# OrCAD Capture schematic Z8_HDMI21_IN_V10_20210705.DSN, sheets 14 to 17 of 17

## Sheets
14 PAGE14-10AX032-(3C&3D): size C
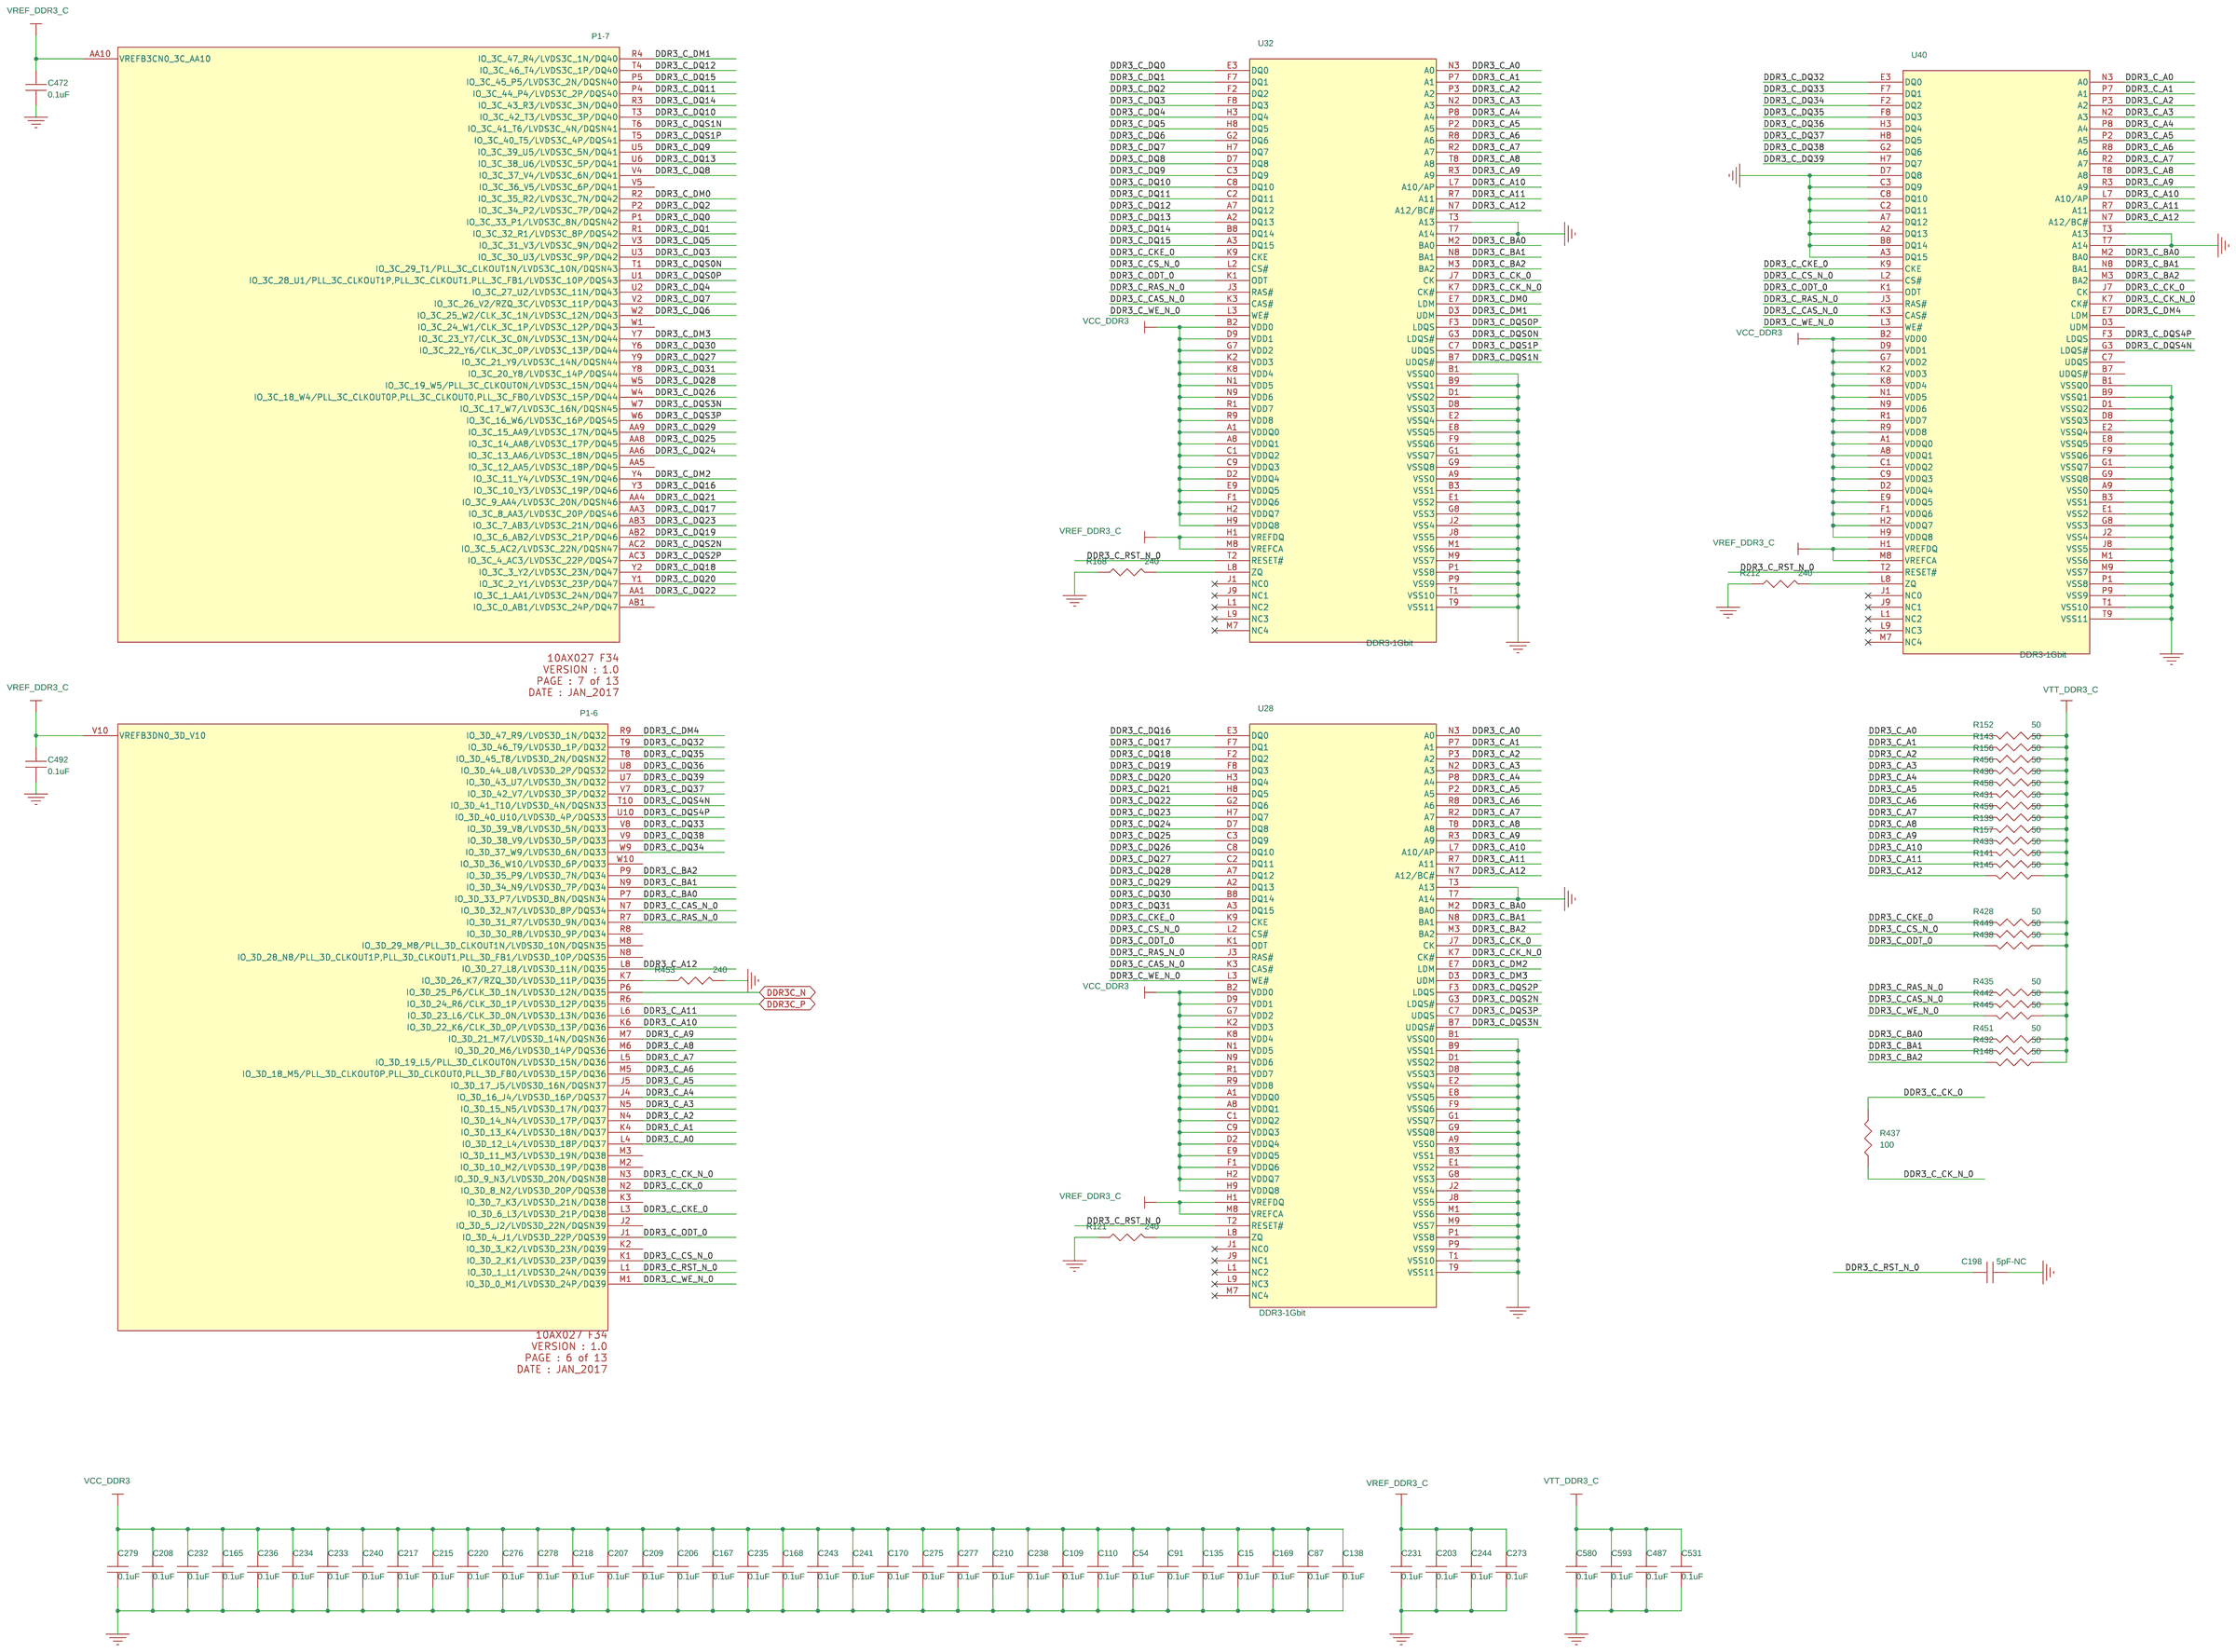
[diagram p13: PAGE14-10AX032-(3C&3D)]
15 PAGE13-10AX032-(3A&3B): size C
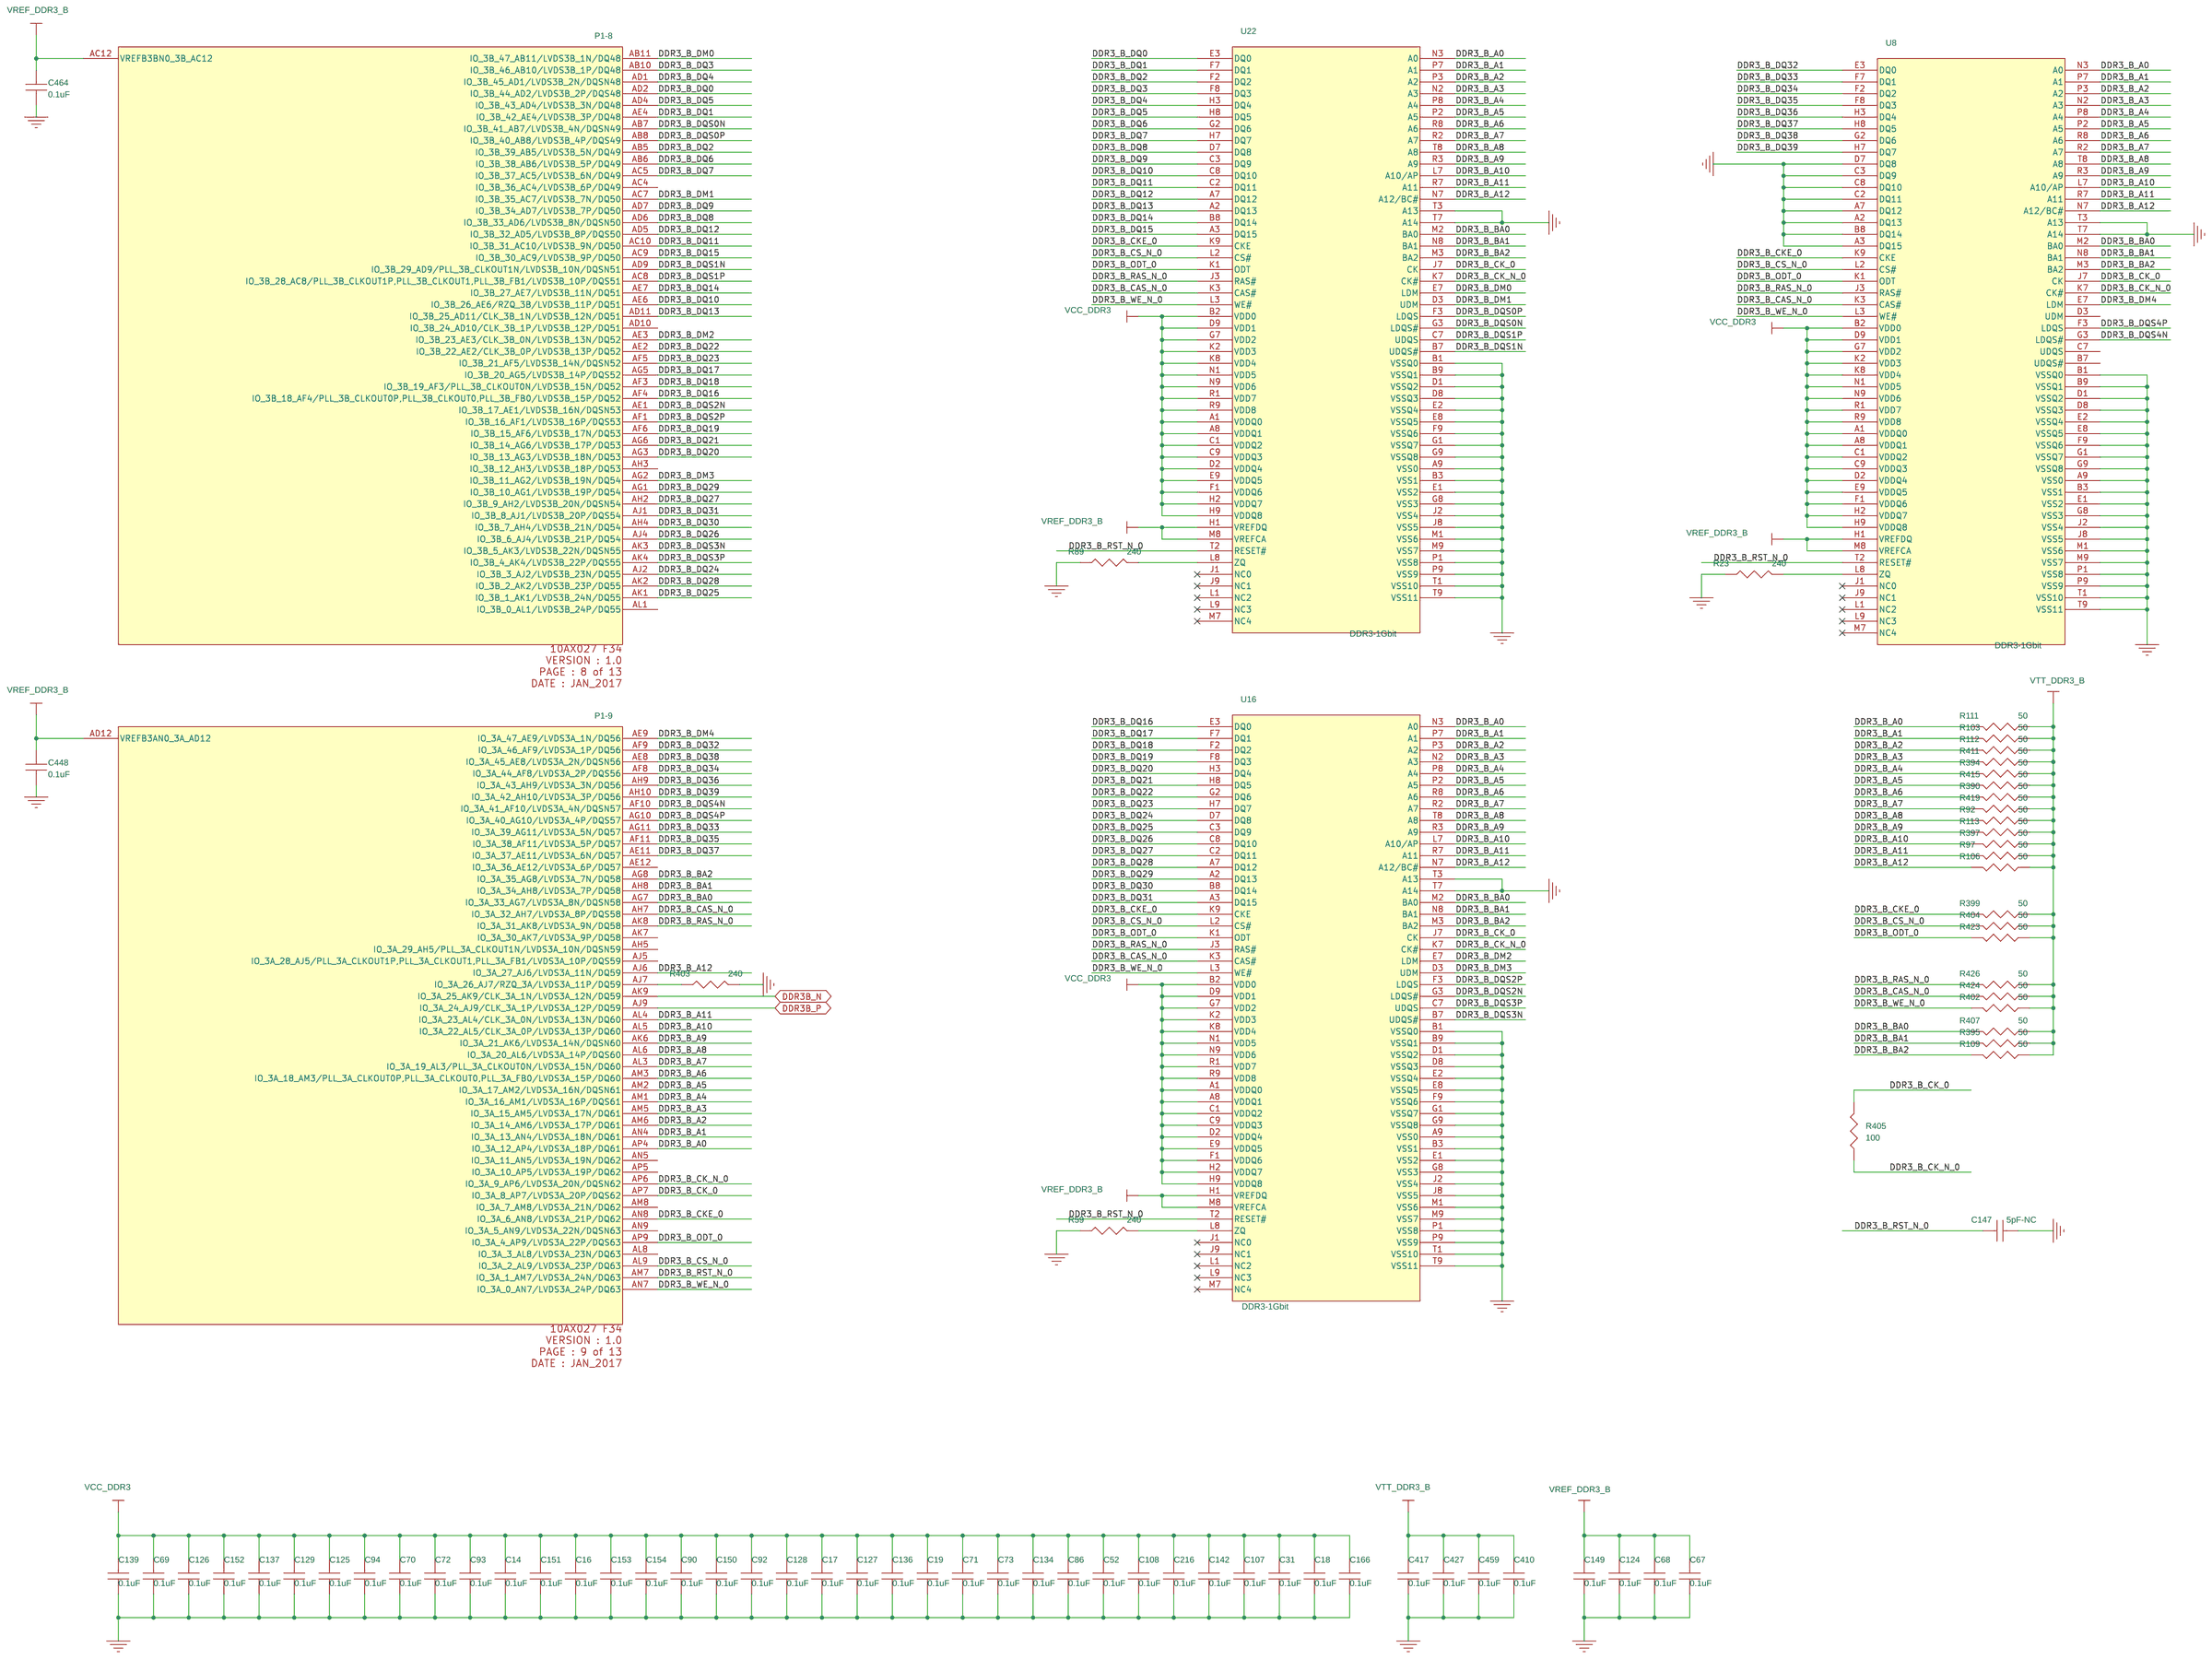
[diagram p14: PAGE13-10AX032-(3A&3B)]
16 PAGE16-10AX032-PWR&GND: size D
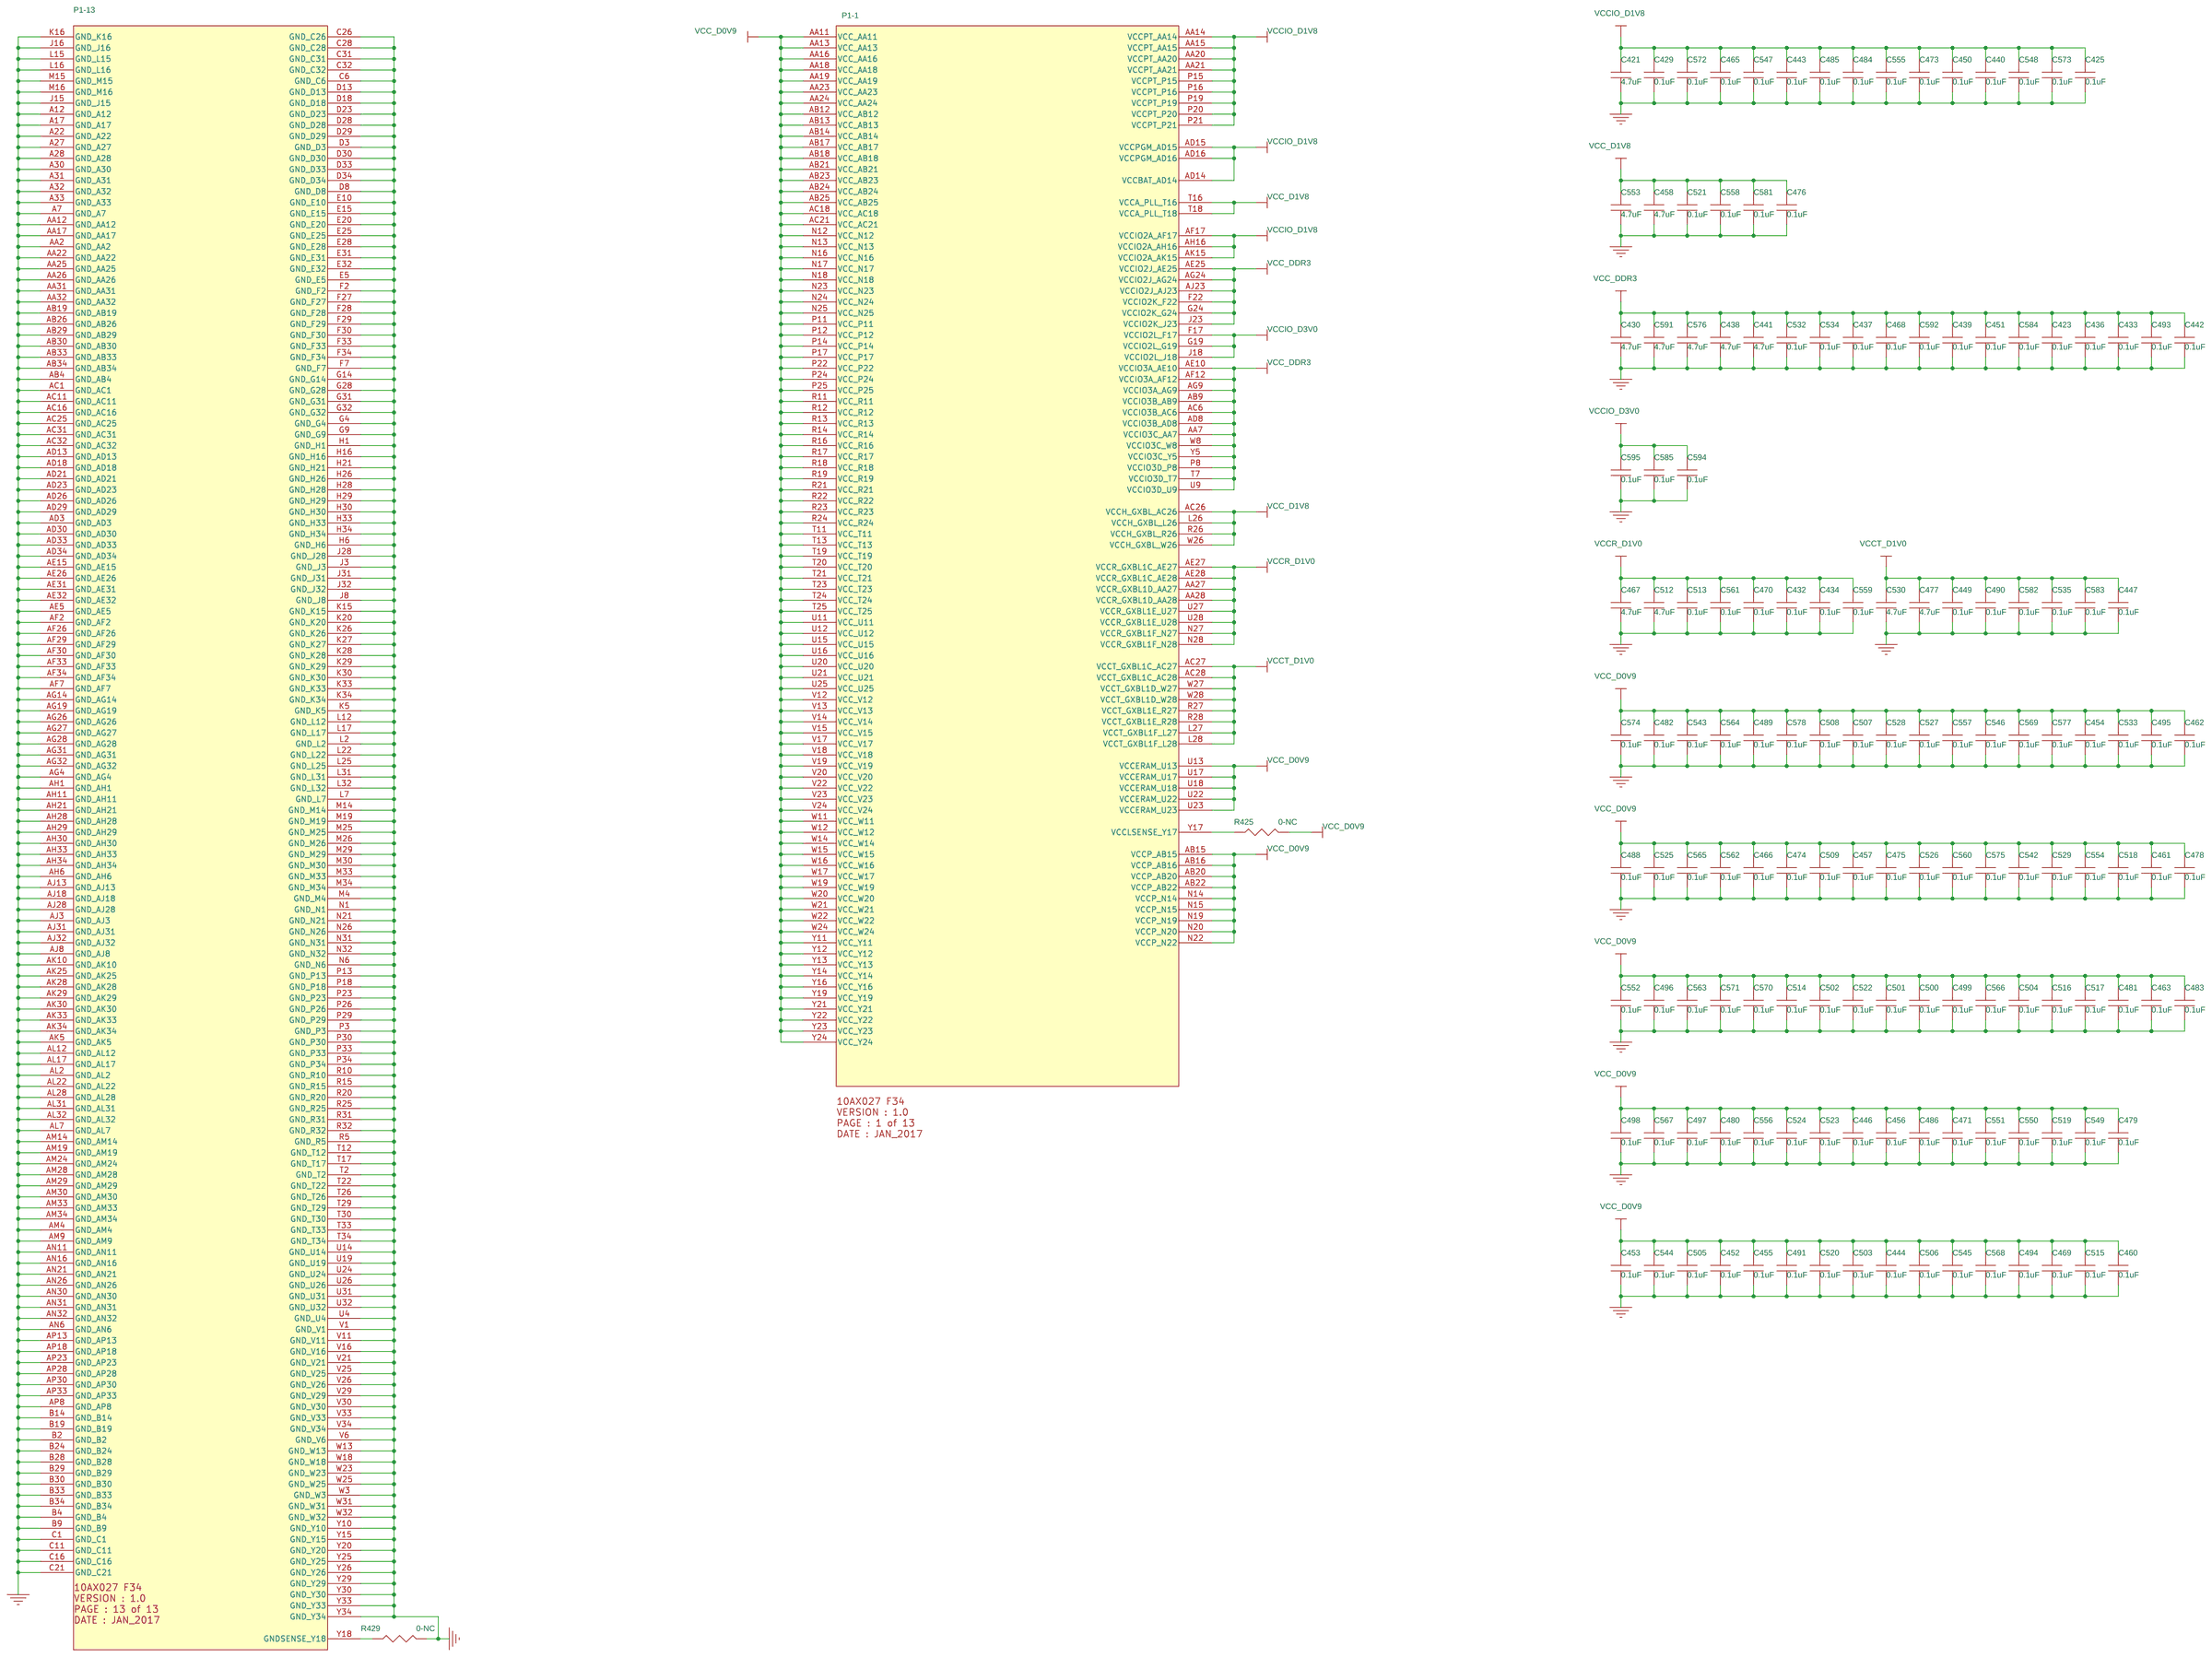
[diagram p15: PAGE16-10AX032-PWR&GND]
17 PAGE03-FPGA PWR: size Custom
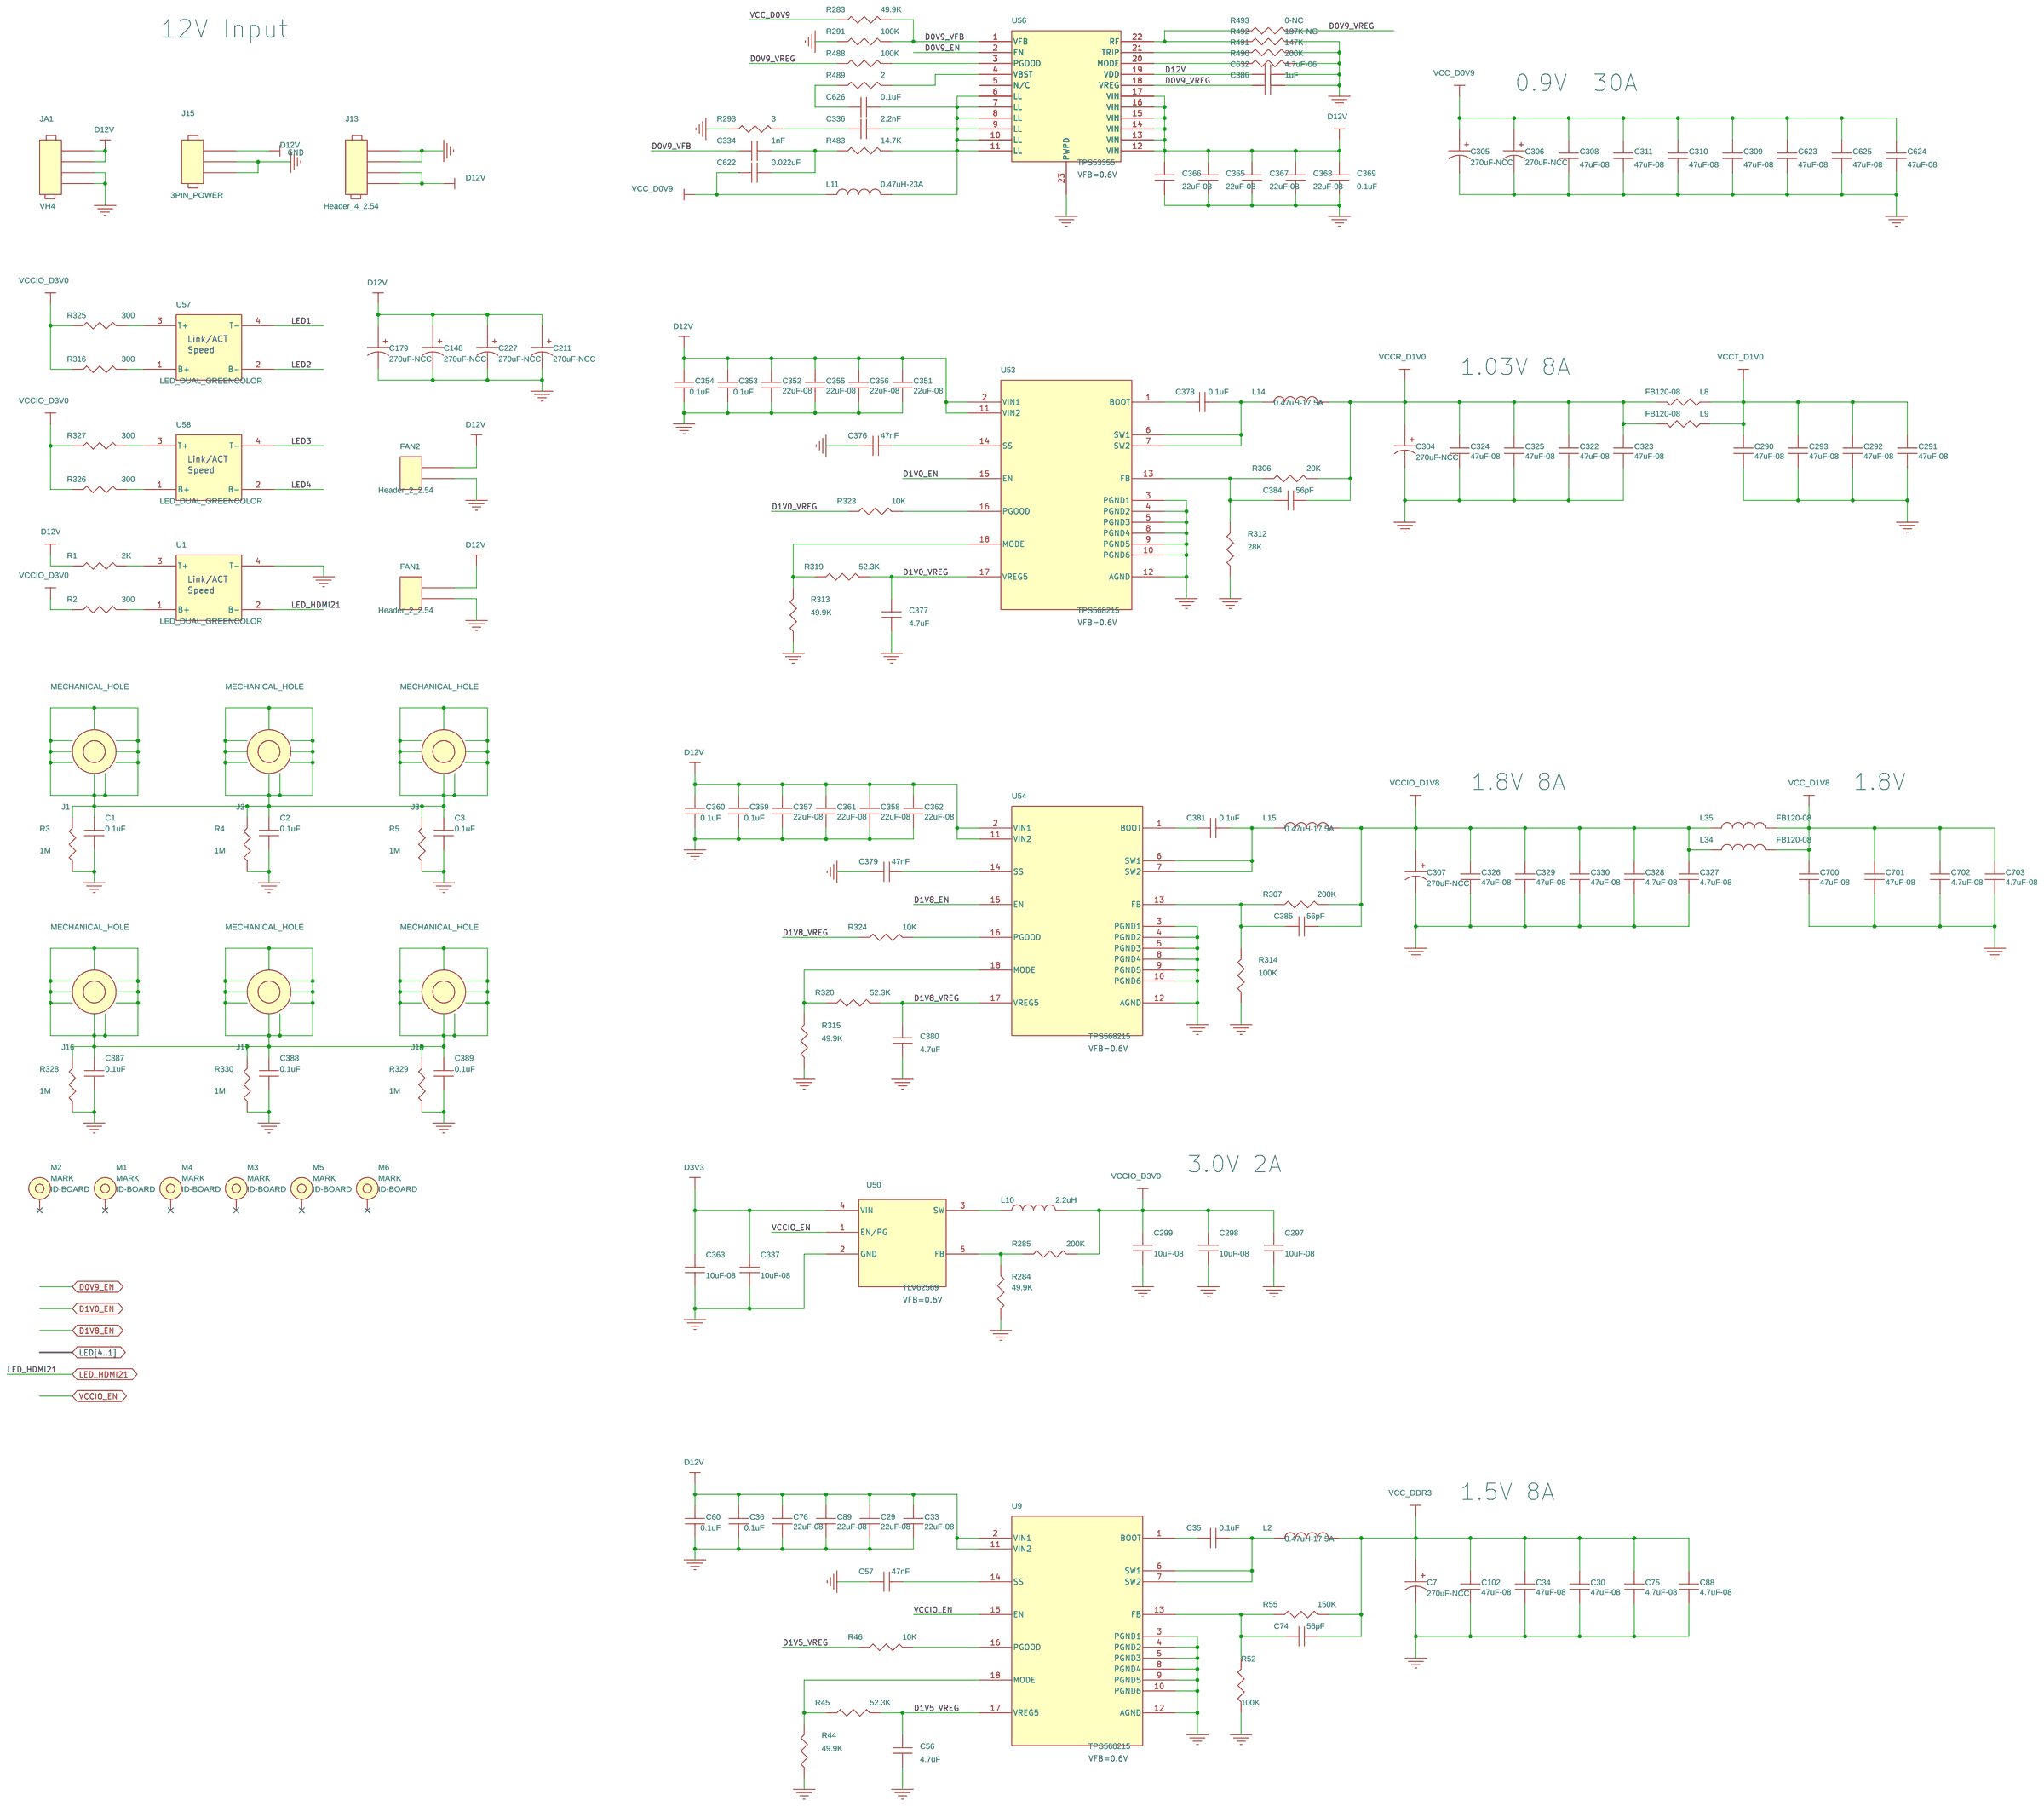
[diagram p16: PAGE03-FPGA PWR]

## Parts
sheet PAGE03-FPGA PWR
C1  0.1uF  [C0402]
C2  0.1uF  [C0402]
C3  0.1uF  [C0402]
C7  270uF-NCC  [cap196_pol_3_5mm]
C29  22uF-08  [C0805]
C30  47uF-08  [C0805]
C33  22uF-08  [C0805]
C34  47uF-08  [C0805]
C35  0.1uF  [C0402]
C36  0.1uF  [C0402]
C56  4.7uF  [C0402]
C57  47nF  [C0402]
C60  0.1uF  [C0402]
C74  56pF  [C0402]
C75  4.7uF-08  [C0603]
C76  22uF-08  [C0805]
C88  4.7uF-08  [C0603]
C89  22uF-08  [C0805]
C102  47uF-08  [C0805]
C148  270uF-NCC  [cap196_pol_3_5mm]
C179  270uF-NCC  [cap196_pol_3_5mm]
C211  270uF-NCC  [cap196_pol_3_5mm]
C227  270uF-NCC  [cap196_pol_3_5mm]
C290  47uF-08  [C0805]
C291  47uF-08  [C0805]
C292  47uF-08  [C0805]
C293  47uF-08  [C0805]
C297  10uF-08  [C0805]
C298  10uF-08  [C0805]
C299  10uF-08  [C0805]
C304  270uF-NCC  [cap196_pol_3_5mm]
C305  270uF-NCC  [cap196_pol_3_5mm]
C306  270uF-NCC  [cap196_pol_3_5mm]
C307  270uF-NCC  [cap196_pol_3_5mm]
C308  47uF-08  [C0805]
C309  47uF-08  [C0805]
C310  47uF-08  [C0805]
C311  47uF-08  [C0805]
C322  47uF-08  [C0805]
C323  47uF-08  [C0805]
C324  47uF-08  [C0805]
C325  47uF-08  [C0805]
C326  47uF-08  [C0805]
C327  4.7uF-08  [C0603]
C328  4.7uF-08  [C0603]
C329  47uF-08  [C0805]
C330  47uF-08  [C0805]
C334  1nF  [C0402]
C336  2.2nF  [C0402]
C337  10uF-08  [C0805]
C351  22uF-08  [C0805]
C352  22uF-08  [C0805]
C353  0.1uF  [C0402]
C354  0.1uF  [C0402]
C355  22uF-08  [C0805]
C356  22uF-08  [C0805]
C357  22uF-08  [C0805]
C358  22uF-08  [C0805]
C359  0.1uF  [C0402]
C360  0.1uF  [C0402]
C361  22uF-08  [C0805]
C362  22uF-08  [C0805]
C363  10uF-08  [C0805]
C365  22uF-08  [C0805]
C366  22uF-08  [C0805]
C367  22uF-08  [C0805]
C368  22uF-08  [C0805]
C369  0.1uF  [C0402]
C376  47nF  [C0402]
C377  4.7uF  [C0402]
C378  0.1uF  [C0402]
C379  47nF  [C0402]
C380  4.7uF  [C0402]
C381  0.1uF  [C0402]
C384  56pF  [C0402]
C385  56pF  [C0402]
C386  1uF  [C0402]
C387  0.1uF  [C0402]
C388  0.1uF  [C0402]
C389  0.1uF  [C0402]
C622  0.022uF  [C0402]
C623  47uF-08  [C0805]
C624  47uF-08  [C0805]
C625  47uF-08  [C0805]
C626  0.1uF  [C0402]
C632  4.7uF-06  [C0603]
C700  47uF-08  [C0805]
C701  47uF-08  [C0805]
C702  4.7uF-08  [C0603]
C703  4.7uF-08  [C0603]
FAN1  Header_2_2.54  [conn1x2_2_54]
FAN2  Header_2_2.54  [conn1x2_2_54]
J1  MECHANICAL_HOLE  [TOOL_1H_8D_C_LC_02]
J2  MECHANICAL_HOLE  [TOOL_1H_8D_C_LC_02]
J3  MECHANICAL_HOLE  [TOOL_1H_8D_C_LC_02]
J13  Header_4_2.54  [conn1x4_2_54]
J15  3PIN_POWER  [3PIN_POWER]
J16  MECHANICAL_HOLE  [TOOL_1H_8D_C_LC_02]
J17  MECHANICAL_HOLE  [TOOL_1H_8D_C_LC_02]
J18  MECHANICAL_HOLE  [TOOL_1H_8D_C_LC_02]
JA1  VH4  [DRILL_1x4_3_96]
L2  0.47uH-17.5A  [l_gfb_58x28]
L8  FB120-08  [R0805]
L9  FB120-08  [R0805]
L10  2.2uH  [IND4X4]
L11  0.47uH-23A  [l_gfb_58x28]
L14  0.47uH-17.5A  [l_gfb_58x28]
L15  0.47uH-17.5A  [l_gfb_58x28]
L34  FB120-08  [R0805]
L35  FB120-08  [R0805]
M1  MARK  [ID-BOARD]
M2  MARK  [ID-BOARD]
M3  MARK  [ID-BOARD]
M4  MARK  [ID-BOARD]
M5  MARK  [ID-BOARD]
M6  MARK  [ID-BOARD]
R1  2K  [R0402]
R2  300  [R0402]
R3  1M  [R0402]
R4  1M  [R0402]
R5  1M  [R0402]
R44  49.9K  [R0402]
R45  52.3K  [R0402]
R46  10K  [R0402]
R52  100K  [R0402]
R55  150K  [R0402]
R283  49.9K  [R0402]
R284  49.9K  [R0402]
R285  200K  [R0402]
R291  100K  [R0402]
R293  3  [R0402]
R306  20K  [R0402]
R307  200K  [R0402]
R312  28K  [R0402]
R313  49.9K  [R0402]
R314  100K  [R0402]
R315  49.9K  [R0402]
R316  300  [R0402]
R319  52.3K  [R0402]
R320  52.3K  [R0402]
R323  10K  [R0402]
R324  10K  [R0402]
R325  300  [R0402]
R326  300  [R0402]
R327  300  [R0402]
R328  1M  [R0402]
R329  1M  [R0402]
R330  1M  [R0402]
R483  14.7K  [R0402]
R488  100K  [R0402]
R489  2  [R0402]
R490  200K  [R0402]
R491  147K  [R0402]
R492  187K-NC  [R0402]
R493  0-NC  [R0402]
U1  LED_DUAL_GREENCOLOR  [LED-4p]
U9  TPS568215  [TPS568215]
U50  TLV62569  [sot23-5]
U53  TPS568215  [TPS568215]
U54  TPS568215  [TPS568215]
U56  TPS53355  [DQP_N22]
U57  LED_DUAL_GREENCOLOR  [LED-4p]
U58  LED_DUAL_GREENCOLOR  [LED-4p]
sheet PAGE12-10AX032-(2K&2J)
P1  10AX027 F34  [BGA1152_PAD18]  (sections -1,-10,-11,-12,-13,-2,-3,-4,-5,-6,-7,-8,-9)
sheet PAGE13-10AX032-(3A&3B)
C14  0.1uF  [C0402]
C16  0.1uF  [C0402]
C17  0.1uF  [C0402]
C18  0.1uF  [C0402]
C19  0.1uF  [C0402]
C31  0.1uF  [C0402]
C52  0.1uF  [C0402]
C67  0.1uF  [C0402]
C68  0.1uF  [C0402]
C69  0.1uF  [C0402]
C70  0.1uF  [C0402]
C71  0.1uF  [C0402]
C72  0.1uF  [C0402]
C73  0.1uF  [C0402]
C86  0.1uF  [C0402]
C90  0.1uF  [C0402]
C92  0.1uF  [C0402]
C93  0.1uF  [C0402]
C94  0.1uF  [C0402]
C107  0.1uF  [C0402]
C108  0.1uF  [C0402]
C124  0.1uF  [C0402]
C125  0.1uF  [C0402]
C126  0.1uF  [C0402]
C127  0.1uF  [C0402]
C128  0.1uF  [C0402]
C129  0.1uF  [C0402]
C134  0.1uF  [C0402]
C136  0.1uF  [C0402]
C137  0.1uF  [C0402]
C139  0.1uF  [C0402]
C142  0.1uF  [C0402]
C147  5pF-NC  [C0402]
C149  0.1uF  [C0402]
C150  0.1uF  [C0402]
C151  0.1uF  [C0402]
C152  0.1uF  [C0402]
C153  0.1uF  [C0402]
C154  0.1uF  [C0402]
C166  0.1uF  [C0402]
C216  0.1uF  [C0402]
C410  0.1uF  [C0402]
C417  0.1uF  [C0402]
C427  0.1uF  [C0402]
C448  0.1uF  [C0402-8]
C459  0.1uF  [C0402]
C464  0.1uF  [C0402-8]
R23  240  [R0402]
R59  240  [R0402]
R89  240  [R0402]
R92  50  [R0402]
R97  50  [R0402]
R103  50  [R0402]
R106  50  [R0402]
R109  50  [R0402]
R111  50  [R0402]
R112  50  [R0402]
R113  50  [R0402]
R390  50  [R0402]
R394  50  [R0402]
R395  50  [R0402]
R397  50  [R0402]
R399  50  [R0402]
R402  50  [R0402]
R403  240  [C0402-8]
R404  50  [R0402]
R405  100  [R0402]
R407  50  [R0402]
R411  50  [R0402]
R415  50  [R0402]
R419  50  [R0402]
R423  50  [R0402]
R424  50  [R0402]
R426  50  [R0402]
U8  DDR3-1Gbit  [fbga96-10x14]
U16  DDR3-1Gbit  [fbga96-10x14]
U22  DDR3-1Gbit  [fbga96-10x14]
sheet PAGE14-10AX032-(3C&3D)
C15  0.1uF  [C0402]
C54  0.1uF  [C0402]
C87  0.1uF  [C0402]
C91  0.1uF  [C0402]
C109  0.1uF  [C0402]
C110  0.1uF  [C0402]
C135  0.1uF  [C0402]
C138  0.1uF  [C0402]
C165  0.1uF  [C0402]
C167  0.1uF  [C0402]
C168  0.1uF  [C0402]
C169  0.1uF  [C0402]
C170  0.1uF  [C0402]
C198  5pF-NC  [C0402]
C203  0.1uF  [C0402]
C206  0.1uF  [C0402]
C207  0.1uF  [C0402]
C208  0.1uF  [C0402]
C209  0.1uF  [C0402]
C210  0.1uF  [C0402]
C215  0.1uF  [C0402]
C217  0.1uF  [C0402]
C218  0.1uF  [C0402]
C220  0.1uF  [C0402]
C231  0.1uF  [C0402]
C232  0.1uF  [C0402]
C233  0.1uF  [C0402]
C234  0.1uF  [C0402]
C235  0.1uF  [C0402]
C236  0.1uF  [C0402]
C238  0.1uF  [C0402]
C240  0.1uF  [C0402]
C241  0.1uF  [C0402]
C243  0.1uF  [C0402]
C244  0.1uF  [C0402]
C273  0.1uF  [C0402]
C275  0.1uF  [C0402]
C276  0.1uF  [C0402]
C277  0.1uF  [C0402]
C278  0.1uF  [C0402]
C279  0.1uF  [C0402]
C472  0.1uF  [C0402-8]
C487  0.1uF  [C0402]
C492  0.1uF  [C0402-8]
C531  0.1uF  [C0402]
C580  0.1uF  [C0402]
C593  0.1uF  [C0402]
R121  240  [R0402]
R139  50  [R0402]
R141  50  [R0402]
R143  50  [R0402]
R145  50  [R0402]
R148  50  [R0402]
R152  50  [R0402]
R156  50  [R0402]
R157  50  [R0402]
R168  240  [R0402]
R212  240  [R0402]
R428  50  [R0402]
R430  50  [R0402]
R431  50  [R0402]
R432  50  [R0402]
R433  50  [R0402]
R435  50  [R0402]
R437  100  [R0402]
R438  50  [R0402]
R442  50  [R0402]
R445  50  [R0402]
R449  50  [R0402]
R451  50  [R0402]
R453  240  [C0402-8]
R456  50  [R0402]
R458  50  [R0402]
R459  50  [R0402]
U28  DDR3-1Gbit  [fbga96-10x14]
U32  DDR3-1Gbit  [fbga96-10x14]
U40  DDR3-1Gbit  [fbga96-10x14]
sheet PAGE16-10AX032-PWR&GND
C421  4.7uF  [C0402-8]
C423  0.1uF  [C0402-8]
C425  0.1uF  [C0402-8]
C429  0.1uF  [C0402-8]
C430  4.7uF  [C0402-8]
C432  0.1uF  [C0402-8]
C433  0.1uF  [C0402-8]
C434  0.1uF  [C0402-8]
C436  0.1uF  [C0402-8]
C437  0.1uF  [C0402-8]
C438  4.7uF  [C0402-8]
C439  0.1uF  [C0402-8]
C440  0.1uF  [C0402-8]
C441  4.7uF  [C0402-8]
C442  0.1uF  [C0402-8]
C443  0.1uF  [C0402-8]
C444  0.1uF  [C0402-8]
C446  0.1uF  [C0402-8]
C447  0.1uF  [C0402-8]
C449  0.1uF  [C0402-8]
C450  0.1uF  [C0402-8]
C451  0.1uF  [C0402-8]
C452  0.1uF  [C0402-8]
C453  0.1uF  [C0402-8]
C454  0.1uF  [C0402-8]
C455  0.1uF  [C0402-8]
C456  0.1uF  [C0402-8]
C457  0.1uF  [C0402-8]
C458  4.7uF  [C0402-8]
C460  0.1uF  [C0402-8]
C461  0.1uF  [C0402-8]
C462  0.1uF  [C0402-8]
C463  0.1uF  [C0402-8]
C465  0.1uF  [C0402-8]
C466  0.1uF  [C0402-8]
C467  4.7uF  [C0402-8]
C468  0.1uF  [C0402-8]
C469  0.1uF  [C0402-8]
C470  0.1uF  [C0402-8]
C471  0.1uF  [C0402-8]
C473  0.1uF  [C0402-8]
C474  0.1uF  [C0402-8]
C475  0.1uF  [C0402-8]
C476  0.1uF  [C0402-8]
C477  4.7uF  [C0402-8]
C478  0.1uF  [C0402-8]
C479  0.1uF  [C0402-8]
C480  0.1uF  [C0402-8]
C481  0.1uF  [C0402-8]
C482  0.1uF  [C0402-8]
C483  0.1uF  [C0402-8]
C484  0.1uF  [C0402-8]
C485  0.1uF  [C0402-8]
C486  0.1uF  [C0402-8]
C488  0.1uF  [C0402-8]
C489  0.1uF  [C0402-8]
C490  0.1uF  [C0402-8]
C491  0.1uF  [C0402-8]
C493  0.1uF  [C0402-8]
C494  0.1uF  [C0402-8]
C495  0.1uF  [C0402-8]
C496  0.1uF  [C0402-8]
C497  0.1uF  [C0402-8]
C498  0.1uF  [C0402-8]
C499  0.1uF  [C0402-8]
C500  0.1uF  [C0402-8]
C501  0.1uF  [C0402-8]
C502  0.1uF  [C0402-8]
C503  0.1uF  [C0402-8]
C504  0.1uF  [C0402-8]
C505  0.1uF  [C0402-8]
C506  0.1uF  [C0402-8]
C507  0.1uF  [C0402-8]
C508  0.1uF  [C0402-8]
C509  0.1uF  [C0402-8]
C512  4.7uF  [C0402-8]
C513  0.1uF  [C0402-8]
C514  0.1uF  [C0402-8]
C515  0.1uF  [C0402-8]
C516  0.1uF  [C0402-8]
C517  0.1uF  [C0402-8]
C518  0.1uF  [C0402-8]
C519  0.1uF  [C0402-8]
C520  0.1uF  [C0402-8]
C521  0.1uF  [C0402-8]
C522  0.1uF  [C0402-8]
C523  0.1uF  [C0402-8]
C524  0.1uF  [C0402-8]
C525  0.1uF  [C0402-8]
C526  0.1uF  [C0402-8]
C527  0.1uF  [C0402-8]
C528  0.1uF  [C0402-8]
C529  0.1uF  [C0402-8]
C530  4.7uF  [C0402-8]
C532  0.1uF  [C0402-8]
C533  0.1uF  [C0402-8]
C534  0.1uF  [C0402-8]
C535  0.1uF  [C0402-8]
C542  0.1uF  [C0402-8]
C543  0.1uF  [C0402-8]
C544  0.1uF  [C0402-8]
C545  0.1uF  [C0402-8]
C546  0.1uF  [C0402-8]
C547  0.1uF  [C0402-8]
C548  0.1uF  [C0402-8]
C549  0.1uF  [C0402-8]
C550  0.1uF  [C0402-8]
C551  0.1uF  [C0402-8]
C552  0.1uF  [C0402-8]
C553  4.7uF  [C0402-8]
C554  0.1uF  [C0402-8]
C555  0.1uF  [C0402-8]
C556  0.1uF  [C0402-8]
C557  0.1uF  [C0402-8]
C558  0.1uF  [C0402-8]
C559  0.1uF  [C0402-8]
C560  0.1uF  [C0402-8]
C561  0.1uF  [C0402-8]
C562  0.1uF  [C0402-8]
C563  0.1uF  [C0402-8]
C564  0.1uF  [C0402-8]
C565  0.1uF  [C0402-8]
C566  0.1uF  [C0402-8]
C567  0.1uF  [C0402-8]
C568  0.1uF  [C0402-8]
C569  0.1uF  [C0402-8]
C570  0.1uF  [C0402-8]
C571  0.1uF  [C0402-8]
C572  0.1uF  [C0402-8]
C573  0.1uF  [C0402-8]
C574  0.1uF  [C0402-8]
C575  0.1uF  [C0402-8]
C576  4.7uF  [C0402-8]
C577  0.1uF  [C0402-8]
C578  0.1uF  [C0402-8]
C581  0.1uF  [C0402-8]
C582  0.1uF  [C0402-8]
C583  0.1uF  [C0402-8]
C584  0.1uF  [C0402-8]
C585  0.1uF  [C0402-8]
C591  4.7uF  [C0402-8]
C592  0.1uF  [C0402-8]
C594  0.1uF  [C0402-8]
C595  0.1uF  [C0402-8]
R425  0-NC  [C0402-8]
R429  0-NC  [C0402-8]

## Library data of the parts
C1-C3 C387-C389 = CAP_NP: ROOM: DVI; VOLTAGE: 25V
C7 C148 C179 C211 C227 C304-C307 = CAP_POL
C14-C19 C29-C31 C33-C36 C52 C54 C56 C57 C60 C67-C76 C86-C94 C102 C107-C110 C124-C129 C134-C139 C142 C147 C149-C154 C165-C170 C198 C203 C206-C210 C215-C218 C220 C231-C236 C238 C240 C241 C243 C244 C273 C275-C279 C290-C293 C297-C299 C308-C311 C322-C330 C334 C336 C337 C351-C363 C369 C376-C381 C384-C386 C410 C417 C421 C423 C425 C427 C429 C430 C432-C434 C436-C444 C446-C509 C512-C535 C542-C578 C580-C585 C591-C595 C622-C626 C632 C700-C703 = CAP_NP
C365-C368 = CAPACITOR_NON-POL
FAN1 FAN2 = CONN_FLEX_5_0
J1-J3 J16-J18 = MECHANICAL_HOLE_0
J13 JA1 = 4_HEADER
J15 = 4_HEADER_0
L2 L10 L11 L14 L15 L34 L35 = L_0
L8 L9 R1-R5 R23 R44-R46 R52 R55 R59 R89 R92 R97 R103 R106 R109 R111-R113 R121 R139 R141 R143 R145 R148 R152 R156 R157 R168 R212 R283-R285 R291 R293 R306 R307 R312-R316 R319 R320 R323-R330 R390 R394 R395 R397 R399 R402-R405 R407 R411 R415 R419 R423-R426 R428-R433 R435 R437 R438 R442 R445 R449 R451 R453 R456 R458 R459 R483 R488-R493 = R
M1-M6 = MARK: MARK Symble; Created by: CZD; Priority: A; RK PN: MARK01
U1 U57 U58 = LED_DUAL_BICOLOR
U9 U53 U54 = TPS54040_0
U50 = TLV62565_0
U56 = TPS53355
P1 = 10AX027_F34_2
U8 U16 U22 U28 U32 U40 = DDR3-512MB

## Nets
D0V9_EN: U56.2(EN) ; also on sheet 8
D0V9_VFB: C334.1 R283.1 R291.2 U56.1(VFB)
D0V9_VREG: C386.1 R488.1 R493.2 U56.18(VREG)
D1V0_EN: U53.15(EN) ; also on sheet 8
D1V0_VREG: C377.1 R319.2 R323.1 U53.17(VREG5)
D1V5_VREG: C56.1 R45.2 R46.1 U9.17(VREG5)
D1V8_EN: U54.15(EN) ; also on sheet 8
D1V8_VREG: C380.1 R320.2 R324.1 U54.17(VREG5)
D3V3: C337.1 C363.1 U50.4(VIN) ; also on sheet 1 2 3 5 6 7 8 10
D12V: C29.1 C33.1 C36.1 C60.1 C76.1 C89.1 C148.1 C179.1 C211.1 C227.1 C351.1 C352.1 C353.1 C354.1 C355.1 C356.1 C357.1 C358.1 C359.1 C360.1 C361.1 C362.1 C365.1 C366.1 C367.1 C368.1 C369.1 C632.1 FAN1.1 FAN2.1 J13.3 J13.4 J15.1 JA1.1 JA1.2 R1.1 U9.2(VIN1) U9.11(VIN2) U53.2(VIN1) U53.11(VIN2) U54.2(VIN1) U54.11(VIN2) U56.12(VIN) U56.13(VIN) U56.14(VIN) U56.15(VIN) U56.16(VIN) U56.17(VIN) U56.19(VDD) ; also on sheet 10 12
GND: C1.2 C2.2 C3.2 C7.2 C14.2 C15.2 C16.2 C17.2 C18.2 C19.2 C29.2 C30.2 C31.2 C33.2 C34.2 C36.2 C52.2 C54.2 C56.2 C57.2 C60.2 C67.2 C68.2 C69.2 C70.2 C71.2 C72.2 C73.2 C75.2 C76.2 C86.2 C87.2 C88.2 C89.2 C90.2 C91.2 C92.2 C93.2 C94.2 C102.2 C107.2 C108.2 C109.2 C110.2 C124.2 C125.2 C126.2 C127.2 C128.2 C129.2 C134.2 C135.2 C136.2 C137.2 C138.2 C139.2 C142.2 C147.2 C148.2 C149.2 C150.2 C151.2 C152.2 C153.2 C154.2 C165.2 C166.2 C167.2 C168.2 C169.2 C170.2 C179.2 C198.2 C203.2 C206.2 C207.2 C208.2 C209.2 C210.2 C211.2 C215.2 C216.2 C217.2 C218.2 C220.2 C227.2 C231.2 C232.2 C233.2 C234.2 C235.2 C236.2 C238.2 C240.2 C241.2 C243.2 C244.2 C273.2 C275.2 C276.2 C277.2 C278.2 C279.2 C290.2 C291.2 C292.2 C293.2 C297.2 C298.2 C299.2 C304.2 C305.2 C306.2 C307.2 C308.2 C309.2 C310.2 C311.2 C322.2 C323.2 C324.2 C325.2 C326.2 C327.2 C328.2 C329.2 C330.2 C337.2 C351.2 C352.2 C353.2 C354.2 C355.2 C356.2 C357.2 C358.2 C359.2 C360.2 C361.2 C362.2 C363.2 C365.2 C366.2 C367.2 C368.2 C369.2 C376.2 C377.2 C379.2 C380.2 C386.2 C387.2 C388.2 C389.2 C410.2 C417.2 C421.2 C423.2 C425.2 C427.2 C429.2 C430.2 C432.2 C433.2 C434.2 C436.2 C437.2 C438.2 C439.2 C440.2 C441.2 C442.2 C443.2 C444.2 C446.2 C447.2 C448.2 C449.2 C450.2 C451.2 C452.2 C453.2 C454.2 C455.2 C456.2 C457.2 C458.2 C459.2 C460.2 C461.2 C462.2 C463.2 C464.2 C465.2 C466.2 C467.2 C468.2 C469.2 C470.2 C471.2 C472.2 C473.2 C474.2 C475.2 C476.2 C477.2 C478.2 C479.2 C480.2 C481.2 C482.2 C483.2 C484.2 C485.2 C486.2 C487.2 C488.2 C489.2 C490.2 C491.2 C492.2 C493.2 C494.2 C495.2 C496.2 C497.2 C498.2 C499.2 C500.2 C501.2 C502.2 C503.2 C504.2 C505.2 C506.2 C507.2 C508.2 C509.2 C512.2 C513.2 C514.2 C515.2 C516.2 C517.2 C518.2 C519.2 C520.2 C521.2 C522.2 C523.2 C524.2 C525.2 C526.2 C527.2 C528.2 C529.2 C530.2 C531.2 C532.2 C533.2 C534.2 C535.2 C542.2 C543.2 C544.2 C545.2 C546.2 C547.2 C548.2 C549.2 C550.2 C551.2 C552.2 C553.2 C554.2 C555.2 C556.2 C557.2 C558.2 C559.2 C560.2 C561.2 C562.2 C563.2 C564.2 C565.2 C566.2 C567.2 C568.2 C569.2 C570.2 C571.2 C572.2 C573.2 C574.2 C575.2 C576.2 C577.2 C578.2 C580.2 C581.2 C582.2 C583.2 C584.2 C585.2 C591.2 C592.2 C593.2 C594.2 C595.2 C623.2 C624.2 C625.2 C632.2 C700.2 C701.2 C702.2 C703.2 FAN1.2 FAN2.2 J13.1 J13.2 J15.2 J15.3 JA1.3 JA1.4 P1.A7(GND) P1.A12(GND) P1.A17(GND) P1.A22(GND) P1.A27(GND) P1.A28(GND) P1.A30(GND) P1.A31(GND) P1.A32(GND) P1.A33(GND) P1.AA2(GND) P1.AA12(GND) P1.AA17(GND) P1.AA22(GND) P1.AA25(GND) P1.AA26(GND) P1.AA31(GND) P1.AA32(GND) P1.AB4(GND) P1.AB19(GND) P1.AB26(GND) P1.AB29(GND) P1.AB30(GND) P1.AB33(GND) P1.AB34(GND) P1.AC1(GND) P1.AC11(GND) P1.AC16(GND) P1.AC25(GND) P1.AC31(GND) P1.AC32(GND) P1.AD3(GND) P1.AD13(GND) P1.AD18(GND) P1.AD21(GND) P1.AD23(GND) P1.AD26(GND) P1.AD29(GND) P1.AD30(GND) P1.AD33(GND) P1.AD34(GND) P1.AE5(GND) P1.AE15(GND) P1.AE26(GND) P1.AE31(GND) P1.AE32(GND) P1.AF2(GND) P1.AF7(GND) P1.AF26(GND) P1.AF29(GND) P1.AF30(GND) P1.AF33(GND) P1.AF34(GND) P1.AG4(GND) P1.AG14(GND) P1.AG19(GND) P1.AG26(GND) P1.AG27(GND) P1.AG28(GND) P1.AG31(GND) P1.AG32(GND) P1.AH1(GND) P1.AH6(GND) P1.AH11(GND) P1.AH21(GND) P1.AH28(GND) P1.AH29(GND) P1.AH30(GND) P1.AH33(GND) P1.AH34(GND) P1.AJ3(GND) P1.AJ8(GND) P1.AJ13(GND) P1.AJ18(GND) P1.AJ28(GND) P1.AJ31(GND) P1.AJ32(GND) P1.AK5(GND) P1.AK10(GND) P1.AK25(GND) P1.AK28(GND) P1.AK29(GND) P1.AK30(GND) P1.AK33(GND) P1.AK34(GND) P1.AL2(GND) P1.AL7(GND) P1.AL12(GND) P1.AL17(GND) P1.AL22(GND) P1.AL28(GND) P1.AL31(GND) P1.AL32(GND) P1.AM4(GND) P1.AM9(GND) P1.AM14(GND) P1.AM19(GND) P1.AM24(GND) P1.AM28(GND) P1.AM29(GND) P1.AM30(GND) P1.AM33(GND) P1.AM34(GND) P1.AN6(GND) P1.AN11(GND) P1.AN16(GND) P1.AN21(GND) P1.AN26(GND) P1.AN30(GND) P1.AN31(GND) P1.AN32(GND) P1.AP8(GND) P1.AP13(GND) P1.AP18(GND) P1.AP23(GND) P1.AP28(GND) P1.AP30(GND) P1.AP33(GND) P1.B2(GND) P1.B4(GND) P1.B9(GND) P1.B14(GND) P1.B19(GND) P1.B24(GND) P1.B28(GND) P1.B29(GND) P1.B30(GND) P1.B33(GND) P1.B34(GND) P1.C1(GND) P1.C6(GND) P1.C11(GND) P1.C16(GND) P1.C21(GND) P1.C26(GND) P1.C28(GND) P1.C31(GND) P1.C32(GND) P1.D3(GND) P1.D8(GND) P1.D13(GND) P1.D18(GND) P1.D23(GND) P1.D28(GND) P1.D29(GND) P1.D30(GND) P1.D33(GND) P1.D34(GND) P1.E5(GND) P1.E10(GND) P1.E15(GND) P1.E20(GND) P1.E25(GND) P1.E28(GND) P1.E31(GND) P1.E32(GND) P1.F2(GND) P1.F7(GND) P1.F27(GND) P1.F28(GND) P1.F29(GND) P1.F30(GND) P1.F33(GND) P1.F34(GND) P1.G4(GND) P1.G9(GND) P1.G14(GND) P1.G28(GND) P1.G31(GND) P1.G32(GND) P1.H1(GND) P1.H6(GND) P1.H16(GND) P1.H21(GND) P1.H26(GND) P1.H28(GND) P1.H29(GND) P1.H30(GND) P1.H33(GND) P1.H34(GND) P1.J3(GND) P1.J8(GND) P1.J15(GND) P1.J16(GND) P1.J28(GND) P1.J31(GND) P1.J32(GND) P1.K5(GND) P1.K15(GND) P1.K16(GND) P1.K20(GND) P1.K26(GND) P1.K27(GND) P1.K28(GND) P1.K29(GND) P1.K30(GND) P1.K33(GND) P1.K34(GND) P1.L2(GND) P1.L7(GND) P1.L12(GND) P1.L15(GND) P1.L16(GND) P1.L17(GND) P1.L22(GND) P1.L25(GND) P1.L31(GND) P1.L32(GND) P1.M4(GND) P1.M14(GND) P1.M15(GND) P1.M16(GND) P1.M19(GND) P1.M25(GND) P1.M26(GND) P1.M29(GND) P1.M30(GND) P1.M33(GND) P1.M34(GND) P1.N1(GND) P1.N6(GND) P1.N21(GND) P1.N26(GND) P1.N31(GND) P1.N32(GND) P1.P3(GND) P1.P13(GND) P1.P18(GND) P1.P23(GND) P1.P26(GND) P1.P29(GND) P1.P30(GND) P1.P33(GND) P1.P34(GND) P1.R5(GND) P1.R10(GND) P1.R15(GND) P1.R20(GND) P1.R25(GND) P1.R31(GND) P1.R32(GND) P1.T2(GND) P1.T12(GND) P1.T17(GND) P1.T22(GND) P1.T26(GND) P1.T29(GND) P1.T30(GND) P1.T33(GND) P1.T34(GND) P1.U4(GND) P1.U14(GND) P1.U19(GND) P1.U24(GND) P1.U26(GND) P1.U31(GND) P1.U32(GND) P1.V1(GND) P1.V6(GND) P1.V11(GND) P1.V16(GND) P1.V21(GND) P1.V25(GND) P1.V26(GND) P1.V29(GND) P1.V30(GND) P1.V33(GND) P1.V34(GND) P1.W3(GND) P1.W13(GND) P1.W18(GND) P1.W23(GND) P1.W25(GND) P1.W31(GND) P1.W32(GND) P1.Y10(GND) P1.Y15(GND) P1.Y20(GND) P1.Y25(GND) P1.Y26(GND) P1.Y29(GND) P1.Y30(GND) P1.Y33(GND) P1.Y34(GND) R3.1 R4.1 R5.1 R23.1 R44.1 R52.1 R59.1 R89.1 R121.1 R168.1 R212.1 R284.2 R291.1 R293.1 R312.1 R313.1 R314.1 R315.1 R328.1 R329.1 R330.1 R403.2 R429.1 R453.2 R490.2 R491.2 R492.2 U1.4(T-) U8.A2(DQ13) U8.A3(DQ15) U8.A7(DQ12) U8.A9(VSS0) U8.B1(VSSQ0) U8.B3(VSS1) U8.B8(DQ14) U8.B9(VSSQ1) U8.C2(DQ11) U8.C3(DQ9) U8.C8(DQ10) U8.D1(VSSQ2) U8.D7(DQ8) U8.D8(VSSQ3) U8.E1(VSS2) U8.E2(VSSQ4) U8.E8(VSSQ5) U8.F9(VSSQ6) U8.G1(VSSQ7) U8.G8(VSS3) U8.G9(VSSQ8) U8.J2(VSS4) U8.J8(VSS5) U8.M1(VSS6) U8.M9(VSS7) U8.P1(VSS8) U8.P9(VSS9) U8.T1(VSS10) U8.T3(A13) U8.T7(A14) U8.T9(VSS11) U9.3(PGND1) U9.4(PGND2) U9.5(PGND3) U9.8(PGND4) U9.9(PGND5) U9.10(PGND6) U9.12(AGND) U16.A9(VSS0) U16.B1(VSSQ0) U16.B3(VSS1) U16.B9(VSSQ1) U16.D1(VSSQ2) U16.D8(VSSQ3) U16.E1(VSS2) U16.E2(VSSQ4) U16.E8(VSSQ5) U16.F9(VSSQ6) U16.G1(VSSQ7) U16.G8(VSS3) U16.G9(VSSQ8) U16.J2(VSS4) U16.J8(VSS5) U16.M1(VSS6) U16.M9(VSS7) U16.P1(VSS8) U16.P9(VSS9) U16.T1(VSS10) U16.T3(A13) U16.T7(A14) U16.T9(VSS11) U22.A9(VSS0) U22.B1(VSSQ0) U22.B3(VSS1) U22.B9(VSSQ1) U22.D1(VSSQ2) U22.D8(VSSQ3) U22.E1(VSS2) U22.E2(VSSQ4) U22.E8(VSSQ5) U22.F9(VSSQ6) U22.G1(VSSQ7) U22.G8(VSS3) U22.G9(VSSQ8) U22.J2(VSS4) U22.J8(VSS5) U22.M1(VSS6) U22.M9(VSS7) U22.P1(VSS8) U22.P9(VSS9) U22.T1(VSS10) U22.T3(A13) U22.T7(A14) U22.T9(VSS11) U28.A9(VSS0) U28.B1(VSSQ0) U28.B3(VSS1) U28.B9(VSSQ1) U28.D1(VSSQ2) U28.D8(VSSQ3) U28.E1(VSS2) U28.E2(VSSQ4) U28.E8(VSSQ5) U28.F9(VSSQ6) U28.G1(VSSQ7) U28.G8(VSS3) U28.G9(VSSQ8) U28.J2(VSS4) U28.J8(VSS5) U28.M1(VSS6) U28.M9(VSS7) U28.P1(VSS8) U28.P9(VSS9) U28.T1(VSS10) U28.T3(A13) U28.T7(A14) U28.T9(VSS11) U32.A9(VSS0) U32.B1(VSSQ0) U32.B3(VSS1) U32.B9(VSSQ1) U32.D1(VSSQ2) U32.D8(VSSQ3) U32.E1(VSS2) U32.E2(VSSQ4) U32.E8(VSSQ5) U32.F9(VSSQ6) U32.G1(VSSQ7) U32.G8(VSS3) U32.G9(VSSQ8) U32.J2(VSS4) U32.J8(VSS5) U32.M1(VSS6) U32.M9(VSS7) U32.P1(VSS8) U32.P9(VSS9) U32.T1(VSS10) U32.T3(A13) U32.T7(A14) U32.T9(VSS11) U40.A2(DQ13) U40.A3(DQ15) U40.A7(DQ12) U40.A9(VSS0) U40.B1(VSSQ0) U40.B3(VSS1) U40.B8(DQ14) U40.B9(VSSQ1) U40.C2(DQ11) U40.C3(DQ9) U40.C8(DQ10) U40.D1(VSSQ2) U40.D7(DQ8) U40.D8(VSSQ3) U40.E1(VSS2) U40.E2(VSSQ4) U40.E8(VSSQ5) U40.F9(VSSQ6) U40.G1(VSSQ7) U40.G8(VSS3) U40.G9(VSSQ8) U40.J2(VSS4) U40.J8(VSS5) U40.M1(VSS6) U40.M9(VSS7) U40.P1(VSS8) U40.P9(VSS9) U40.T1(VSS10) U40.T3(A13) U40.T7(A14) U40.T9(VSS11) U50.2(GND) U53.3(PGND1) U53.4(PGND2) U53.5(PGND3) U53.8(PGND4) U53.9(PGND5) U53.10(PGND6) U53.12(AGND) U54.3(PGND1) U54.4(PGND2) U54.5(PGND3) U54.8(PGND4) U54.9(PGND5) U54.10(PGND6) U54.12(AGND) U56.23(PWPD) ; also on sheet 1 2 3 4 5 6 7 8 10 12 13
VCC_D0V9: C305.1 C306.1 C308.1 C309.1 C310.1 C311.1 C444.1 C446.1 C452.1 C453.1 C454.1 C455.1 C456.1 C457.1 C460.1 C461.1 C462.1 C463.1 C466.1 C469.1 C471.1 C474.1 C475.1 C478.1 C479.1 C480.1 C481.1 C482.1 C483.1 C486.1 C488.1 C489.1 C491.1 C494.1 C495.1 C496.1 C497.1 C498.1 C499.1 C500.1 C501.1 C502.1 C503.1 C504.1 C505.1 C506.1 C507.1 C508.1 C509.1 C514.1 C515.1 C516.1 C517.1 C518.1 C519.1 C520.1 C522.1 C523.1 C524.1 C525.1 C526.1 C527.1 C528.1 C529.1 C533.1 C542.1 C543.1 C544.1 C545.1 C546.1 C549.1 C550.1 C551.1 C552.1 C554.1 C556.1 C557.1 C560.1 C562.1 C563.1 C564.1 C565.1 C566.1 C567.1 C568.1 C569.1 C570.1 C571.1 C574.1 C575.1 C577.1 C578.1 C622.1 C623.1 C624.1 C625.1 L11.1 P1.AA11(VCC) P1.AA13(VCC) P1.AA16(VCC) P1.AA18(VCC) P1.AA19(VCC) P1.AA23(VCC) P1.AA24(VCC) P1.AB12(VCC) P1.AB13(VCC) P1.AB14(VCC) P1.AB15(VCCP) P1.AB16(VCCP) P1.AB17(VCC) P1.AB18(VCC) P1.AB20(VCCP) P1.AB21(VCC) P1.AB22(VCCP) P1.AB23(VCC) P1.AB24(VCC) P1.AB25(VCC) P1.AC18(VCC) P1.AC21(VCC) P1.N12(VCC) P1.N13(VCC) P1.N14(VCCP) P1.N15(VCCP) P1.N16(VCC) P1.N17(VCC) P1.N18(VCC) P1.N19(VCCP) P1.N20(VCCP) P1.N22(VCCP) P1.N23(VCC) P1.N24(VCC) P1.N25(VCC) P1.P11(VCC) P1.P12(VCC) P1.P14(VCC) P1.P17(VCC) P1.P22(VCC) P1.P24(VCC) P1.P25(VCC) P1.R11(VCC) P1.R12(VCC) P1.R13(VCC) P1.R14(VCC) P1.R16(VCC) P1.R17(VCC) P1.R18(VCC) P1.R19(VCC) P1.R21(VCC) P1.R22(VCC) P1.R23(VCC) P1.R24(VCC) P1.T11(VCC) P1.T13(VCC) P1.T19(VCC) P1.T20(VCC) P1.T21(VCC) P1.T23(VCC) P1.T24(VCC) P1.T25(VCC) P1.U11(VCC) P1.U12(VCC) P1.U13(VCCERAM) P1.U15(VCC) P1.U16(VCC) P1.U17(VCCERAM) P1.U18(VCCERAM) P1.U20(VCC) P1.U21(VCC) P1.U22(VCCERAM) P1.U23(VCCERAM) P1.U25(VCC) P1.V12(VCC) P1.V13(VCC) P1.V14(VCC) P1.V15(VCC) P1.V17(VCC) P1.V18(VCC) P1.V19(VCC) P1.V20(VCC) P1.V22(VCC) P1.V23(VCC) P1.V24(VCC) P1.W11(VCC) P1.W12(VCC) P1.W14(VCC) P1.W15(VCC) P1.W16(VCC) P1.W17(VCC) P1.W19(VCC) P1.W20(VCC) P1.W21(VCC) P1.W22(VCC) P1.W24(VCC) P1.Y11(VCC) P1.Y12(VCC) P1.Y13(VCC) P1.Y14(VCC) P1.Y16(VCC) P1.Y19(VCC) P1.Y21(VCC) P1.Y22(VCC) P1.Y23(VCC) P1.Y24(VCC) R283.2 R425.1 ; also on sheet 13
VCC_D1V8: C458.1 C476.1 C521.1 C553.1 C558.1 C581.1 C700.1 C701.1 C702.1 C703.1 L34.2 L35.2 P1.AC26(VCCH_GXBL) P1.L26(VCCH_GXBL) P1.R26(VCCH_GXBL) P1.T16(VCCA_PLL) P1.T18(VCCA_PLL) P1.W26(VCCH_GXBL)
VCC_DDR3: C7.1 C14.1 C15.1 C16.1 C17.1 C18.1 C19.1 C30.1 C31.1 C34.1 C52.1 C54.1 C69.1 C70.1 C71.1 C72.1 C73.1 C74.1 C75.1 C86.1 C87.1 C88.1 C90.1 C91.1 C92.1 C93.1 C94.1 C102.1 C107.1 C108.1 C109.1 C110.1 C125.1 C126.1 C127.1 C128.1 C129.1 C134.1 C135.1 C136.1 C137.1 C138.1 C139.1 C142.1 C150.1 C151.1 C152.1 C153.1 C154.1 C165.1 C166.1 C167.1 C168.1 C169.1 C170.1 C206.1 C207.1 C208.1 C209.1 C210.1 C215.1 C216.1 C217.1 C218.1 C220.1 C232.1 C233.1 C234.1 C235.1 C236.1 C238.1 C240.1 C241.1 C243.1 C275.1 C276.1 C277.1 C278.1 C279.1 C423.1 C430.1 C433.1 C436.1 C437.1 C438.1 C439.1 C441.1 C442.1 C451.1 C468.1 C493.1 C532.1 C534.1 C576.1 C584.1 C591.1 C592.1 L2.2 P1.AA7(VCCIO3C) P1.AB9(VCCIO3B) P1.AC6(VCCIO3B) P1.AD8(VCCIO3B) P1.AE10(VCCIO3A) P1.AE25(VCCIO2J) P1.AF12(VCCIO3A) P1.AG9(VCCIO3A) P1.AG24(VCCIO2J) P1.AJ23(VCCIO2J) P1.F22(VCCIO2K) P1.G24(VCCIO2K) P1.J23(VCCIO2K) P1.P8(VCCIO3D) P1.T7(VCCIO3D) P1.U9(VCCIO3D) P1.W8(VCCIO3C) P1.Y5(VCCIO3C) R55.2 U8.A1(VDDQ0) U8.A8(VDDQ1) U8.B2(VDD0) U8.C1(VDDQ2) U8.C9(VDDQ3) U8.D2(VDDQ4) U8.D9(VDD1) U8.E9(VDDQ5) U8.F1(VDDQ6) U8.G7(VDD2) U8.H2(VDDQ7) U8.H9(VDDQ8) U8.K2(VDD3) U8.K8(VDD4) U8.N1(VDD5) U8.N9(VDD6) U8.R1(VDD7) U8.R9(VDD8) U16.A1(VDDQ0) U16.A8(VDDQ1) U16.B2(VDD0) U16.C1(VDDQ2) U16.C9(VDDQ3) U16.D2(VDDQ4) U16.D9(VDD1) U16.E9(VDDQ5) U16.F1(VDDQ6) U16.G7(VDD2) U16.H2(VDDQ7) U16.H9(VDDQ8) U16.K2(VDD3) U16.K8(VDD4) U16.N1(VDD5) U16.N9(VDD6) U16.R1(VDD7) U16.R9(VDD8) U22.A1(VDDQ0) U22.A8(VDDQ1) U22.B2(VDD0) U22.C1(VDDQ2) U22.C9(VDDQ3) U22.D2(VDDQ4) U22.D9(VDD1) U22.E9(VDDQ5) U22.F1(VDDQ6) U22.G7(VDD2) U22.H2(VDDQ7) U22.H9(VDDQ8) U22.K2(VDD3) U22.K8(VDD4) U22.N1(VDD5) U22.N9(VDD6) U22.R1(VDD7) U22.R9(VDD8) U28.A1(VDDQ0) U28.A8(VDDQ1) U28.B2(VDD0) U28.C1(VDDQ2) U28.C9(VDDQ3) U28.D2(VDDQ4) U28.D9(VDD1) U28.E9(VDDQ5) U28.F1(VDDQ6) U28.G7(VDD2) U28.H2(VDDQ7) U28.H9(VDDQ8) U28.K2(VDD3) U28.K8(VDD4) U28.N1(VDD5) U28.N9(VDD6) U28.R1(VDD7) U28.R9(VDD8) U32.A1(VDDQ0) U32.A8(VDDQ1) U32.B2(VDD0) U32.C1(VDDQ2) U32.C9(VDDQ3) U32.D2(VDDQ4) U32.D9(VDD1) U32.E9(VDDQ5) U32.F1(VDDQ6) U32.G7(VDD2) U32.H2(VDDQ7) U32.H9(VDDQ8) U32.K2(VDD3) U32.K8(VDD4) U32.N1(VDD5) U32.N9(VDD6) U32.R1(VDD7) U32.R9(VDD8) U40.A1(VDDQ0) U40.A8(VDDQ1) U40.B2(VDD0) U40.C1(VDDQ2) U40.C9(VDDQ3) U40.D2(VDDQ4) U40.D9(VDD1) U40.E9(VDDQ5) U40.F1(VDDQ6) U40.G7(VDD2) U40.H2(VDDQ7) U40.H9(VDDQ8) U40.K2(VDD3) U40.K8(VDD4) U40.N1(VDD5) U40.N9(VDD6) U40.R1(VDD7) U40.R9(VDD8) ; also on sheet 4 10
VCCIO_D1V8: C307.1 C326.1 C327.1 C328.1 C329.1 C330.1 C385.1 C421.1 C425.1 C429.1 C440.1 C443.1 C450.1 C465.1 C473.1 C484.1 C485.1 C547.1 C548.1 C555.1 C572.1 C573.1 L15.2 L34.1 L35.1 P1.AA14(VCCPT) P1.AA15(VCCPT) P1.AA20(VCCPT) P1.AA21(VCCPT) P1.AD14(VCCBAT) P1.AD15(VCCPGM) P1.AD16(VCCPGM) P1.AF17(VCCIO2A) P1.AH16(VCCIO2A) P1.AK15(VCCIO2A) P1.P15(VCCPT) P1.P16(VCCPT) P1.P19(VCCPT) P1.P20(VCCPT) P1.P21(VCCPT) R307.2 ; also on sheet 13
VCCIO_D3V0: C297.1 C298.1 C299.1 C585.1 C594.1 C595.1 L10.2 P1.F17(VCCIO2L) P1.G19(VCCIO2L) P1.J18(VCCIO2L) R2.1 R285.2 R316.1 R325.1 R326.1 R327.1
VCCIO_EN: U9.15(EN) U50.1(EN/PG) ; also on sheet 8
VCCR_D1V0: C304.1 C322.1 C323.1 C324.1 C325.1 C384.1 C432.1 C434.1 C467.1 C470.1 C512.1 C513.1 C559.1 C561.1 L8.1 L9.1 L14.2 P1.AA27(VCCR_GXBL1D) P1.AA28(VCCR_GXBL1D) P1.AE27(VCCR_GXBL1C) P1.AE28(VCCR_GXBL1C) P1.N27(VCCR_GXBL1F) P1.N28(VCCR_GXBL1F) P1.U27(VCCR_GXBL1E) P1.U28(VCCR_GXBL1E) R306.2
VCCT_D1V0: C290.1 C291.1 C292.1 C293.1 C447.1 C449.1 C477.1 C490.1 C530.1 C535.1 C582.1 C583.1 L8.2 L9.2 P1.AC27(VCCT_GXBL1C) P1.AC28(VCCT_GXBL1C) P1.L27(VCCT_GXBL1F) P1.L28(VCCT_GXBL1F) P1.R27(VCCT_GXBL1E) P1.R28(VCCT_GXBL1E) P1.W27(VCCT_GXBL1D) P1.W28(VCCT_GXBL1D)
DDR3_B_A0: P1.AP4(IO_3A_12_AP4/LVDS3A_18P/DQ61) R111.2 U8.N3(A0) U16.N3(A0) U22.N3(A0)
DDR3_B_A1: P1.AN4(IO_3A_13_AN4/LVDS3A_18N/DQ61) R103.2 U8.P7(A1) U16.P7(A1) U22.P7(A1)
DDR3_B_A2: P1.AM6(IO_3A_14_AM6/LVDS3A_17P/DQ61) R112.2 U8.P3(A2) U16.P3(A2) U22.P3(A2)
DDR3_B_A3: P1.AM5(IO_3A_15_AM5/LVDS3A_17N/DQ61) R411.2 U8.N2(A3) U16.N2(A3) U22.N2(A3)
DDR3_B_A4: P1.AM1(IO_3A_16_AM1/LVDS3A_16P/DQS61) R394.2 U8.P8(A4) U16.P8(A4) U22.P8(A4)
DDR3_B_A5: P1.AM2(IO_3A_17_AM2/LVDS3A_16N/DQSN61) R415.2 U8.P2(A5) U16.P2(A5) U22.P2(A5)
DDR3_B_A6: P1.AM3(IO_3A_18_AM3/PLL_3A_CLKOUT0P,PLL_3A_CLKOUT0,PLL_3A_FB0/LVDS3A_15P/DQ60) R390.2 U8.R8(A6) U16.R8(A6) U22.R8(A6)
DDR3_B_A7: P1.AL3(IO_3A_19_AL3/PLL_3A_CLKOUT0N/LVDS3A_15N/DQ60) R419.2 U8.R2(A7) U16.R2(A7) U22.R2(A7)
DDR3_B_A8: P1.AL6(IO_3A_20_AL6/LVDS3A_14P/DQS60) R92.2 U8.T8(A8) U16.T8(A8) U22.T8(A8)
DDR3_B_A9: P1.AK6(IO_3A_21_AK6/LVDS3A_14N/DQSN60) R113.2 U8.R3(A9) U16.R3(A9) U22.R3(A9)
DDR3_B_A10: P1.AL5(IO_3A_22_AL5/CLK_3A_0P/LVDS3A_13P/DQ60) R397.2 U8.L7(A10/AP) U16.L7(A10/AP) U22.L7(A10/AP)
DDR3_B_A11: P1.AL4(IO_3A_23_AL4/CLK_3A_0N/LVDS3A_13N/DQ60) R97.2 U8.R7(A11) U16.R7(A11) U22.R7(A11)
DDR3_B_A12: P1.AJ6(IO_3A_27_AJ6/LVDS3A_11N/DQ59) R106.2 U8.N7(A12/BC#) U16.N7(A12/BC#) U22.N7(A12/BC#)
DDR3_B_BA0: P1.AG7(IO_3A_33_AG7/LVDS3A_8N/DQSN58) R407.2 U8.M2(BA0) U16.M2(BA0) U22.M2(BA0)
DDR3_B_BA1: P1.AH8(IO_3A_34_AH8/LVDS3A_7P/DQ58) R395.2 U8.N8(BA1) U16.N8(BA1) U22.N8(BA1)
DDR3_B_BA2: P1.AG8(IO_3A_35_AG8/LVDS3A_7N/DQ58) R109.2 U8.M3(BA2) U16.M3(BA2) U22.M3(BA2)
DDR3_B_CAS_N_0: P1.AH7(IO_3A_32_AH7/LVDS3A_8P/DQS58) R424.2 U8.K3(CAS#) U16.K3(CAS#) U22.K3(CAS#)
DDR3_B_CK_0: P1.AP7(IO_3A_8_AP7/LVDS3A_20P/DQS62) R405.2 U8.J7(CK) U16.J7(CK) U22.J7(CK)
DDR3_B_CK_N_0: P1.AP6(IO_3A_9_AP6/LVDS3A_20N/DQSN62) R405.1 U8.K7(CK#) U16.K7(CK#) U22.K7(CK#)
DDR3_B_CKE_0: P1.AN8(IO_3A_6_AN8/LVDS3A_21P/DQ62) R399.2 U8.K9(CKE) U16.K9(CKE) U22.K9(CKE)
DDR3_B_CS_N_0: P1.AL9(IO_3A_2_AL9/LVDS3A_23P/DQ63) R404.2 U8.L2(CS#) U16.L2(CS#) U22.L2(CS#)
DDR3_B_DM0: P1.AB11(IO_3B_47_AB11/LVDS3B_1N/DQ48) U22.E7(LDM)
DDR3_B_DM1: P1.AC7(IO_3B_35_AC7/LVDS3B_7N/DQ50) U22.D3(UDM)
DDR3_B_DM2: P1.AE3(IO_3B_23_AE3/CLK_3B_0N/LVDS3B_13N/DQ52) U16.E7(LDM)
DDR3_B_DM3: P1.AG2(IO_3B_11_AG2/LVDS3B_19N/DQ54) U16.D3(UDM)
DDR3_B_DM4: P1.AE9(IO_3A_47_AE9/LVDS3A_1N/DQ56) U8.E7(LDM)
DDR3_B_DQ0: P1.AD2(IO_3B_44_AD2/LVDS3B_2P/DQS48) U22.E3(DQ0)
DDR3_B_DQ1: P1.AE4(IO_3B_42_AE4/LVDS3B_3P/DQ48) U22.F7(DQ1)
DDR3_B_DQ2: P1.AB5(IO_3B_39_AB5/LVDS3B_5N/DQ49) U22.F2(DQ2)
DDR3_B_DQ3: P1.AB10(IO_3B_46_AB10/LVDS3B_1P/DQ48) U22.F8(DQ3)
DDR3_B_DQ4: P1.AD1(IO_3B_45_AD1/LVDS3B_2N/DQSN48) U22.H3(DQ4)
DDR3_B_DQ5: P1.AD4(IO_3B_43_AD4/LVDS3B_3N/DQ48) U22.H8(DQ5)
DDR3_B_DQ6: P1.AB6(IO_3B_38_AB6/LVDS3B_5P/DQ49) U22.G2(DQ6)
DDR3_B_DQ7: P1.AC5(IO_3B_37_AC5/LVDS3B_6N/DQ49) U22.H7(DQ7)
DDR3_B_DQ8: P1.AD6(IO_3B_33_AD6/LVDS3B_8N/DQSN50) U22.D7(DQ8)
DDR3_B_DQ9: P1.AD7(IO_3B_34_AD7/LVDS3B_7P/DQ50) U22.C3(DQ9)
DDR3_B_DQ10: P1.AE6(IO_3B_26_AE6/RZQ_3B/LVDS3B_11P/DQ51) U22.C8(DQ10)
DDR3_B_DQ11: P1.AC10(IO_3B_31_AC10/LVDS3B_9N/DQ50) U22.C2(DQ11)
DDR3_B_DQ12: P1.AD5(IO_3B_32_AD5/LVDS3B_8P/DQS50) U22.A7(DQ12)
DDR3_B_DQ13: P1.AD11(IO_3B_25_AD11/CLK_3B_1N/LVDS3B_12N/DQ51) U22.A2(DQ13)
DDR3_B_DQ14: P1.AE7(IO_3B_27_AE7/LVDS3B_11N/DQ51) U22.B8(DQ14)
DDR3_B_DQ15: P1.AC9(IO_3B_30_AC9/LVDS3B_9P/DQ50) U22.A3(DQ15)
DDR3_B_DQ16: P1.AF4(IO_3B_18_AF4/PLL_3B_CLKOUT0P,PLL_3B_CLKOUT0,PLL_3B_FB0/LVDS3B_15P/DQ52) U16.E3(DQ0)
DDR3_B_DQ17: P1.AG5(IO_3B_20_AG5/LVDS3B_14P/DQS52) U16.F7(DQ1)
DDR3_B_DQ18: P1.AF3(IO_3B_19_AF3/PLL_3B_CLKOUT0N/LVDS3B_15N/DQ52) U16.F2(DQ2)
DDR3_B_DQ19: P1.AF6(IO_3B_15_AF6/LVDS3B_17N/DQ53) U16.F8(DQ3)
DDR3_B_DQ20: P1.AG3(IO_3B_13_AG3/LVDS3B_18N/DQ53) U16.H3(DQ4)
DDR3_B_DQ21: P1.AG6(IO_3B_14_AG6/LVDS3B_17P/DQ53) U16.H8(DQ5)
DDR3_B_DQ22: P1.AE2(IO_3B_22_AE2/CLK_3B_0P/LVDS3B_13P/DQ52) U16.G2(DQ6)
DDR3_B_DQ23: P1.AF5(IO_3B_21_AF5/LVDS3B_14N/DQSN52) U16.H7(DQ7)
DDR3_B_DQ24: P1.AJ2(IO_3B_3_AJ2/LVDS3B_23N/DQ55) U16.D7(DQ8)
DDR3_B_DQ25: P1.AK1(IO_3B_1_AK1/LVDS3B_24N/DQ55) U16.C3(DQ9)
DDR3_B_DQ26: P1.AJ4(IO_3B_6_AJ4/LVDS3B_21P/DQ54) U16.C8(DQ10)
DDR3_B_DQ27: P1.AH2(IO_3B_9_AH2/LVDS3B_20N/DQSN54) U16.C2(DQ11)
DDR3_B_DQ28: P1.AK2(IO_3B_2_AK2/LVDS3B_23P/DQ55) U16.A7(DQ12)
DDR3_B_DQ29: P1.AG1(IO_3B_10_AG1/LVDS3B_19P/DQ54) U16.A2(DQ13)
DDR3_B_DQ30: P1.AH4(IO_3B_7_AH4/LVDS3B_21N/DQ54) U16.B8(DQ14)
DDR3_B_DQ31: P1.AJ1(IO_3B_8_AJ1/LVDS3B_20P/DQS54) U16.A3(DQ15)
DDR3_B_DQ32: P1.AF9(IO_3A_46_AF9/LVDS3A_1P/DQ56) U8.E3(DQ0)
DDR3_B_DQ33: P1.AG11(IO_3A_39_AG11/LVDS3A_5N/DQ57) U8.F7(DQ1)
DDR3_B_DQ34: P1.AF8(IO_3A_44_AF8/LVDS3A_2P/DQS56) U8.F2(DQ2)
DDR3_B_DQ35: P1.AF11(IO_3A_38_AF11/LVDS3A_5P/DQ57) U8.F8(DQ3)
DDR3_B_DQ36: P1.AH9(IO_3A_43_AH9/LVDS3A_3N/DQ56) U8.H3(DQ4)
DDR3_B_DQ37: P1.AE11(IO_3A_37_AE11/LVDS3A_6N/DQ57) U8.H8(DQ5)
DDR3_B_DQ38: P1.AE8(IO_3A_45_AE8/LVDS3A_2N/DQSN56) U8.G2(DQ6)
DDR3_B_DQ39: P1.AH10(IO_3A_42_AH10/LVDS3A_3P/DQ56) U8.H7(DQ7)
DDR3_B_DQS0N: P1.AB7(IO_3B_41_AB7/LVDS3B_4N/DQSN49) U22.G3(LDQS#)
DDR3_B_DQS0P: P1.AB8(IO_3B_40_AB8/LVDS3B_4P/DQS49) U22.F3(LDQS)
DDR3_B_DQS1N: P1.AD9(IO_3B_29_AD9/PLL_3B_CLKOUT1N/LVDS3B_10N/DQSN51) U22.B7(UDQS#)
DDR3_B_DQS1P: P1.AC8(IO_3B_28_AC8/PLL_3B_CLKOUT1P,PLL_3B_CLKOUT1,PLL_3B_FB1/LVDS3B_10P/DQS51) U22.C7(UDQS)
DDR3_B_DQS2N: P1.AE1(IO_3B_17_AE1/LVDS3B_16N/DQSN53) U16.G3(LDQS#)
DDR3_B_DQS2P: P1.AF1(IO_3B_16_AF1/LVDS3B_16P/DQS53) U16.F3(LDQS)
DDR3_B_DQS3N: P1.AK3(IO_3B_5_AK3/LVDS3B_22N/DQSN55) U16.B7(UDQS#)
DDR3_B_DQS3P: P1.AK4(IO_3B_4_AK4/LVDS3B_22P/DQS55) U16.C7(UDQS)
DDR3_B_DQS4N: P1.AF10(IO_3A_41_AF10/LVDS3A_4N/DQSN57) U8.G3(LDQS#)
DDR3_B_DQS4P: P1.AG10(IO_3A_40_AG10/LVDS3A_4P/DQS57) U8.F3(LDQS)
DDR3_B_ODT_0: P1.AP9(IO_3A_4_AP9/LVDS3A_22P/DQS63) R423.2 U8.K1(ODT) U16.K1(ODT) U22.K1(ODT)
DDR3_B_RAS_N_0: P1.AK8(IO_3A_31_AK8/LVDS3A_9N/DQ58) R426.2 U8.J3(RAS#) U16.J3(RAS#) U22.J3(RAS#)
DDR3_B_RST_N_0: C147.1 P1.AM7(IO_3A_1_AM7/LVDS3A_24N/DQ63) U8.T2(RESET#) U16.T2(RESET#) U22.T2(RESET#)
DDR3_B_WE_N_0: P1.AN7(IO_3A_0_AN7/LVDS3A_24P/DQ63) R402.2 U8.L3(WE#) U16.L3(WE#) U22.L3(WE#)
DDR3_C_A0: P1.L4(IO_3D_12_L4/LVDS3D_18P/DQ37) R152.2 U28.N3(A0) U32.N3(A0) U40.N3(A0)
DDR3_C_A1: P1.K4(IO_3D_13_K4/LVDS3D_18N/DQ37) R143.2 U28.P7(A1) U32.P7(A1) U40.P7(A1)
DDR3_C_A2: P1.N4(IO_3D_14_N4/LVDS3D_17P/DQ37) R156.2 U28.P3(A2) U32.P3(A2) U40.P3(A2)
DDR3_C_A3: P1.N5(IO_3D_15_N5/LVDS3D_17N/DQ37) R456.2 U28.N2(A3) U32.N2(A3) U40.N2(A3)
DDR3_C_A4: P1.J4(IO_3D_16_J4/LVDS3D_16P/DQS37) R430.2 U28.P8(A4) U32.P8(A4) U40.P8(A4)
DDR3_C_A5: P1.J5(IO_3D_17_J5/LVDS3D_16N/DQSN37) R458.2 U28.P2(A5) U32.P2(A5) U40.P2(A5)
DDR3_C_A6: P1.M5(IO_3D_18_M5/PLL_3D_CLKOUT0P,PLL_3D_CLKOUT0,PLL_3D_FB0/LVDS3D_15P/DQ36) R431.2 U28.R8(A6) U32.R8(A6) U40.R8(A6)
DDR3_C_A7: P1.L5(IO_3D_19_L5/PLL_3D_CLKOUT0N/LVDS3D_15N/DQ36) R459.2 U28.R2(A7) U32.R2(A7) U40.R2(A7)
DDR3_C_A8: P1.M6(IO_3D_20_M6/LVDS3D_14P/DQS36) R139.2 U28.T8(A8) U32.T8(A8) U40.T8(A8)
DDR3_C_A9: P1.M7(IO_3D_21_M7/LVDS3D_14N/DQSN36) R157.2 U28.R3(A9) U32.R3(A9) U40.R3(A9)
DDR3_C_A10: P1.K6(IO_3D_22_K6/CLK_3D_0P/LVDS3D_13P/DQ36) R433.2 U28.L7(A10/AP) U32.L7(A10/AP) U40.L7(A10/AP)
DDR3_C_A11: P1.L6(IO_3D_23_L6/CLK_3D_0N/LVDS3D_13N/DQ36) R141.2 U28.R7(A11) U32.R7(A11) U40.R7(A11)
DDR3_C_A12: P1.L8(IO_3D_27_L8/LVDS3D_11N/DQ35) R145.2 U28.N7(A12/BC#) U32.N7(A12/BC#) U40.N7(A12/BC#)
DDR3_C_BA0: P1.P7(IO_3D_33_P7/LVDS3D_8N/DQSN34) R451.2 U28.M2(BA0) U32.M2(BA0) U40.M2(BA0)
DDR3_C_BA1: P1.N9(IO_3D_34_N9/LVDS3D_7P/DQ34) R432.2 U28.N8(BA1) U32.N8(BA1) U40.N8(BA1)
DDR3_C_BA2: P1.P9(IO_3D_35_P9/LVDS3D_7N/DQ34) R148.2 U28.M3(BA2) U32.M3(BA2) U40.M3(BA2)
DDR3_C_CAS_N_0: P1.N7(IO_3D_32_N7/LVDS3D_8P/DQS34) R442.2 U28.K3(CAS#) U32.K3(CAS#) U40.K3(CAS#)
DDR3_C_CK_0: P1.N2(IO_3D_8_N2/LVDS3D_20P/DQS38) R437.2 U28.J7(CK) U32.J7(CK) U40.J7(CK)
DDR3_C_CK_N_0: P1.N3(IO_3D_9_N3/LVDS3D_20N/DQSN38) R437.1 U28.K7(CK#) U32.K7(CK#) U40.K7(CK#)
DDR3_C_CKE_0: P1.L3(IO_3D_6_L3/LVDS3D_21P/DQ38) R428.2 U28.K9(CKE) U32.K9(CKE) U40.K9(CKE)
DDR3_C_CS_N_0: P1.K1(IO_3D_2_K1/LVDS3D_23P/DQ39) R449.2 U28.L2(CS#) U32.L2(CS#) U40.L2(CS#)
DDR3_C_DM0: P1.R2(IO_3C_35_R2/LVDS3C_7N/DQ42) U32.E7(LDM)
DDR3_C_DM1: P1.R4(IO_3C_47_R4/LVDS3C_1N/DQ40) U32.D3(UDM)
DDR3_C_DM2: P1.Y4(IO_3C_11_Y4/LVDS3C_19N/DQ46) U28.E7(LDM)
DDR3_C_DM3: P1.Y7(IO_3C_23_Y7/CLK_3C_0N/LVDS3C_13N/DQ44) U28.D3(UDM)
DDR3_C_DM4: P1.R9(IO_3D_47_R9/LVDS3D_1N/DQ32) U40.E7(LDM)
DDR3_C_DQ0: P1.P1(IO_3C_33_P1/LVDS3C_8N/DQSN42) U32.E3(DQ0)
DDR3_C_DQ1: P1.R1(IO_3C_32_R1/LVDS3C_8P/DQS42) U32.F7(DQ1)
DDR3_C_DQ2: P1.P2(IO_3C_34_P2/LVDS3C_7P/DQ42) U32.F2(DQ2)
DDR3_C_DQ3: P1.U3(IO_3C_30_U3/LVDS3C_9P/DQ42) U32.F8(DQ3)
DDR3_C_DQ4: P1.U2(IO_3C_27_U2/LVDS3C_11N/DQ43) U32.H3(DQ4)
DDR3_C_DQ5: P1.V3(IO_3C_31_V3/LVDS3C_9N/DQ42) U32.H8(DQ5)
DDR3_C_DQ6: P1.W2(IO_3C_25_W2/CLK_3C_1N/LVDS3C_12N/DQ43) U32.G2(DQ6)
DDR3_C_DQ7: P1.V2(IO_3C_26_V2/RZQ_3C/LVDS3C_11P/DQ43) U32.H7(DQ7)
DDR3_C_DQ8: P1.V4(IO_3C_37_V4/LVDS3C_6N/DQ41) U32.D7(DQ8)
DDR3_C_DQ9: P1.U5(IO_3C_39_U5/LVDS3C_5N/DQ41) U32.C3(DQ9)
DDR3_C_DQ10: P1.T3(IO_3C_42_T3/LVDS3C_3P/DQ40) U32.C8(DQ10)
DDR3_C_DQ11: P1.P4(IO_3C_44_P4/LVDS3C_2P/DQS40) U32.C2(DQ11)
DDR3_C_DQ12: P1.T4(IO_3C_46_T4/LVDS3C_1P/DQ40) U32.A7(DQ12)
DDR3_C_DQ13: P1.U6(IO_3C_38_U6/LVDS3C_5P/DQ41) U32.A2(DQ13)
DDR3_C_DQ14: P1.R3(IO_3C_43_R3/LVDS3C_3N/DQ40) U32.B8(DQ14)
DDR3_C_DQ15: P1.P5(IO_3C_45_P5/LVDS3C_2N/DQSN40) U32.A3(DQ15)
DDR3_C_DQ16: P1.Y3(IO_3C_10_Y3/LVDS3C_19P/DQ46) U28.E3(DQ0)
DDR3_C_DQ17: P1.AA3(IO_3C_8_AA3/LVDS3C_20P/DQS46) U28.F7(DQ1)
DDR3_C_DQ18: P1.Y2(IO_3C_3_Y2/LVDS3C_23N/DQ47) U28.F2(DQ2)
DDR3_C_DQ19: P1.AB2(IO_3C_6_AB2/LVDS3C_21P/DQ46) U28.F8(DQ3)
DDR3_C_DQ20: P1.Y1(IO_3C_2_Y1/LVDS3C_23P/DQ47) U28.H3(DQ4)
DDR3_C_DQ21: P1.AA4(IO_3C_9_AA4/LVDS3C_20N/DQSN46) U28.H8(DQ5)
DDR3_C_DQ22: P1.AA1(IO_3C_1_AA1/LVDS3C_24N/DQ47) U28.G2(DQ6)
DDR3_C_DQ23: P1.AB3(IO_3C_7_AB3/LVDS3C_21N/DQ46) U28.H7(DQ7)
DDR3_C_DQ24: P1.AA6(IO_3C_13_AA6/LVDS3C_18N/DQ45) U28.D7(DQ8)
DDR3_C_DQ25: P1.AA8(IO_3C_14_AA8/LVDS3C_17P/DQ45) U28.C3(DQ9)
DDR3_C_DQ26: P1.W4(IO_3C_18_W4/PLL_3C_CLKOUT0P,PLL_3C_CLKOUT0,PLL_3C_FB0/LVDS3C_15P/DQ44) U28.C8(DQ10)
DDR3_C_DQ27: P1.Y9(IO_3C_21_Y9/LVDS3C_14N/DQSN44) U28.C2(DQ11)
DDR3_C_DQ28: P1.W5(IO_3C_19_W5/PLL_3C_CLKOUT0N/LVDS3C_15N/DQ44) U28.A7(DQ12)
DDR3_C_DQ29: P1.AA9(IO_3C_15_AA9/LVDS3C_17N/DQ45) U28.A2(DQ13)
DDR3_C_DQ30: P1.Y6(IO_3C_22_Y6/CLK_3C_0P/LVDS3C_13P/DQ44) U28.B8(DQ14)
DDR3_C_DQ31: P1.Y8(IO_3C_20_Y8/LVDS3C_14P/DQS44) U28.A3(DQ15)
DDR3_C_DQ32: P1.T9(IO_3D_46_T9/LVDS3D_1P/DQ32) U40.E3(DQ0)
DDR3_C_DQ33: P1.V8(IO_3D_39_V8/LVDS3D_5N/DQ33) U40.F7(DQ1)
DDR3_C_DQ34: P1.W9(IO_3D_37_W9/LVDS3D_6N/DQ33) U40.F2(DQ2)
DDR3_C_DQ35: P1.T8(IO_3D_45_T8/LVDS3D_2N/DQSN32) U40.F8(DQ3)
DDR3_C_DQ36: P1.U8(IO_3D_44_U8/LVDS3D_2P/DQS32) U40.H3(DQ4)
DDR3_C_DQ37: P1.V7(IO_3D_42_V7/LVDS3D_3P/DQ32) U40.H8(DQ5)
DDR3_C_DQ38: P1.V9(IO_3D_38_V9/LVDS3D_5P/DQ33) U40.G2(DQ6)
DDR3_C_DQ39: P1.U7(IO_3D_43_U7/LVDS3D_3N/DQ32) U40.H7(DQ7)
DDR3_C_DQS0N: P1.T1(IO_3C_29_T1/PLL_3C_CLKOUT1N/LVDS3C_10N/DQSN43) U32.G3(LDQS#)
DDR3_C_DQS0P: P1.U1(IO_3C_28_U1/PLL_3C_CLKOUT1P,PLL_3C_CLKOUT1,PLL_3C_FB1/LVDS3C_10P/DQS43) U32.F3(LDQS)
DDR3_C_DQS1N: P1.T6(IO_3C_41_T6/LVDS3C_4N/DQSN41) U32.B7(UDQS#)
DDR3_C_DQS1P: P1.T5(IO_3C_40_T5/LVDS3C_4P/DQS41) U32.C7(UDQS)
DDR3_C_DQS2N: P1.AC2(IO_3C_5_AC2/LVDS3C_22N/DQSN47) U28.G3(LDQS#)
DDR3_C_DQS2P: P1.AC3(IO_3C_4_AC3/LVDS3C_22P/DQS47) U28.F3(LDQS)
DDR3_C_DQS3N: P1.W7(IO_3C_17_W7/LVDS3C_16N/DQSN45) U28.B7(UDQS#)
DDR3_C_DQS3P: P1.W6(IO_3C_16_W6/LVDS3C_16P/DQS45) U28.C7(UDQS)
DDR3_C_DQS4N: P1.T10(IO_3D_41_T10/LVDS3D_4N/DQSN33) U40.G3(LDQS#)
DDR3_C_DQS4P: P1.U10(IO_3D_40_U10/LVDS3D_4P/DQS33) U40.F3(LDQS)
DDR3_C_ODT_0: P1.J1(IO_3D_4_J1/LVDS3D_22P/DQS39) R438.2 U28.K1(ODT) U32.K1(ODT) U40.K1(ODT)
DDR3_C_RAS_N_0: P1.R7(IO_3D_31_R7/LVDS3D_9N/DQ34) R435.2 U28.J3(RAS#) U32.J3(RAS#) U40.J3(RAS#)
DDR3_C_RST_N_0: C198.1 P1.L1(IO_3D_1_L1/LVDS3D_24N/DQ39) U28.T2(RESET#) U32.T2(RESET#) U40.T2(RESET#)
DDR3_C_WE_N_0: P1.M1(IO_3D_0_M1/LVDS3D_24P/DQ39) R445.2 U28.L3(WE#) U32.L3(WE#) U40.L3(WE#)
DDR3B_N: P1.AK9(IO_3A_25_AK9/CLK_3A_1N/LVDS3A_12N/DQ59) ; also on sheet 5
DDR3B_P: P1.AJ9(IO_3A_24_AJ9/CLK_3A_1P/LVDS3A_12P/DQ59) ; also on sheet 5
DDR3C_N: P1.P6(IO_3D_25_P6/CLK_3D_1N/LVDS3D_12N/DQ35) ; also on sheet 5
DDR3C_P: P1.R6(IO_3D_24_R6/CLK_3D_1P/LVDS3D_12P/DQ35) ; also on sheet 5
LED1: U57.4(T-) ; also on sheet 13
LED2: U57.2(B-) ; also on sheet 13
LED3: U58.4(T-) ; also on sheet 13
LED4: U58.2(B-) ; also on sheet 13
LED_HDMI21: U1.2(B-) ; also on sheet 13
VREF_DDR3_B: C67.1 C68.1 C124.1 C149.1 C448.1 C464.1 P1.AC12(VREFB3BN0_3B) P1.AD12(VREFB3AN0_3A) U8.H1(VREFDQ) U8.M8(VREFCA) U16.H1(VREFDQ) U16.M8(VREFCA) U22.H1(VREFDQ) U22.M8(VREFCA) ; also on sheet 10
VREF_DDR3_C: C203.1 C231.1 C244.1 C273.1 C472.1 C492.1 P1.AA10(VREFB3CN0_3C) P1.V10(VREFB3DN0_3D) U28.H1(VREFDQ) U28.M8(VREFCA) U32.H1(VREFDQ) U32.M8(VREFCA) U40.H1(VREFDQ) U40.M8(VREFCA) ; also on sheet 10
VTT_DDR3_B: C410.1 C417.1 C427.1 C459.1 R92.1 R97.1 R103.1 R106.1 R109.1 R111.1 R112.1 R113.1 R390.1 R394.1 R395.1 R397.1 R399.1 R402.1 R404.1 R407.1 R411.1 R415.1 R419.1 R423.1 R424.1 R426.1 ; also on sheet 10
VTT_DDR3_C: C487.1 C531.1 C580.1 C593.1 R139.1 R141.1 R143.1 R145.1 R148.1 R152.1 R156.1 R157.1 R428.1 R430.1 R431.1 R432.1 R433.1 R435.1 R438.1 R442.1 R445.1 R449.1 R451.1 R456.1 R458.1 R459.1 ; also on sheet 10
N22030137: C1.1 C2.1 C3.1 J1.1 J1.2 J1.3 J1.4 J1.5 J1.6 J1.7 J1.8 J1.9 J2.1 J2.2 J2.3 J2.4 J2.5 J2.6 J2.7 J2.8 J2.9 J3.1 J3.2 J3.3 J3.4 J3.5 J3.6 J3.7 J3.8 J3.9 R3.2 R4.2 R5.2
N22030618: C384.2 R306.1 R312.2 U53.13(FB)
N22030676: R323.2 U53.16(PGOOD)
N22030684: R313.2 R319.1 U53.18(MODE)
N22030720: C378.1 U53.1(BOOT)
N22030722: C378.2 L14.1 U53.6(SW1) U53.7(SW2)
N22030830: C376.1 U53.14(SS)
N22030983: R492.1 R493.1 U56.22(RF)
N22031161: C334.2 C622.2 R483.1
N22031163: C336.2 C626.2 L11.2 R483.2 U56.6(LL) U56.7(LL) U56.8(LL) U56.9(LL) U56.10(LL) U56.11(LL)
N22031238: R325.2 U57.3(T+)
N22031240: R316.2 U57.1(B+)
N22031335: R488.2 U56.3(PGOOD)
N22031337: R489.2 U56.4(VBST)
N22031349: C336.1 R293.2
N22031384: R491.1 U56.21(TRIP)
N22031400: R490.1 U56.20(MODE)
N22031488: C626.1 R489.1
N22031700: C387.1 C388.1 C389.1 J16.1 J16.2 J16.3 J16.4 J16.5 J16.6 J16.7 J16.8 J16.9 J17.1 J17.2 J17.3 J17.4 J17.5 J17.6 J17.7 J17.8 J17.9 J18.1 J18.2 J18.3 J18.4 J18.5 J18.6 J18.7 J18.8 J18.9 R328.2 R329.2 R330.2
N22061318: R23.2 U8.L8(ZQ)
N22061537: P1.AJ7(IO_3A_26_AJ7/RZQ_3A/LVDS3A_11P/DQ59) R403.1
N22061744: R59.2 U16.L8(ZQ)
N22062524: R89.2 U22.L8(ZQ)
N22067825: P1.K7(IO_3D_26_K7/RZQ_3D/LVDS3D_11P/DQ35) R453.1
N22068466: R212.2 U40.L8(ZQ)
N22069069: R121.2 U28.L8(ZQ)
N22069811: R168.2 U32.L8(ZQ)
N22082350: P1.Y18(GNDSENSE) R429.2
N22082686: P1.Y17(VCCLSENSE) R425.2
N22090777: R327.2 U58.3(T+)
N22090779: R326.2 U58.1(B+)
N22449821: R315.2 R320.1 U54.18(MODE)
N22449835: C381.1 U54.1(BOOT)
N22449837: C381.2 L15.1 U54.6(SW1) U54.7(SW2)
N22449845: C385.2 R307.1 R314.2 U54.13(FB)
N22449937: C379.1 U54.14(SS)
N22450190: R324.2 U54.16(PGOOD)
N22768217: R44.2 R45.1 U9.18(MODE)
N22768239: C35.1 U9.1(BOOT)
N22768241: C35.2 L2.1 U9.6(SW1) U9.7(SW2)
N22768257: C74.2 R52.2 R55.1 U9.13(FB)
N22768337: C57.1 U9.14(SS)
N22768591: R46.2 U9.16(PGOOD)
N22769636: R284.1 R285.1 U50.5(FB)
N22769670: L10.1 U50.3(SW)
N22958186: R1.2 U1.3(T+)
N22958370: R2.2 U1.1(B+)

Not connected (* = marked no-connect by the designer): M1 1*; M2 1*; M3 1*; M4 1*; M5 1*; M6 1*; P1 AA5(IO_3C_12_AA5/LVDS3C_18P/DQ45) AB1(IO_3C_0_AB1/LVDS3C_24P/DQ47) AC4(IO_3B_36_AC4/LVDS3B_6P/DQ49) AD10(IO_3B_24_AD10/CLK_3B_1P/LVDS3B_12P/DQ51) AE12(IO_3A_36_AE12/LVDS3A_6P/DQ57) AH3(IO_3B_12_AH3/LVDS3B_18P/DQ53) AH5(IO_3A_29_AH5/PLL_3A_CLKOUT1N/LVDS3A_10N/DQSN59) AJ5(IO_3A_28_AJ5/PLL_3A_CLKOUT1P,PLL_3A_CLKOUT1,PLL_3A_FB1/LVDS3A_10P/DQS59) AK7(IO_3A_30_AK7/LVDS3A_9P/DQ58) AL1(IO_3B_0_AL1/LVDS3B_24P/DQ55) AL8(IO_3A_3_AL8/LVDS3A_23N/DQ63) AM8(IO_3A_7_AM8/LVDS3A_21N/DQ62) AN5(IO_3A_11_AN5/LVDS3A_19N/DQ62) AN9(IO_3A_5_AN9/LVDS3A_22N/DQSN63) AP5(IO_3A_10_AP5/LVDS3A_19P/DQ62) J2(IO_3D_5_J2/LVDS3D_22N/DQSN39) K2(IO_3D_3_K2/LVDS3D_23N/DQ39) K3(IO_3D_7_K3/LVDS3D_21N/DQ38) M2(IO_3D_10_M2/LVDS3D_19P/DQ38) M3(IO_3D_11_M3/LVDS3D_19N/DQ38) M8(IO_3D_29_M8/PLL_3D_CLKOUT1N/LVDS3D_10N/DQSN35) N8(IO_3D_28_N8/PLL_3D_CLKOUT1P,PLL_3D_CLKOUT1,PLL_3D_FB1/LVDS3D_10P/DQS35) R8(IO_3D_30_R8/LVDS3D_9P/DQ34) V5(IO_3C_36_V5/LVDS3C_6P/DQ41) W1(IO_3C_24_W1/CLK_3C_1P/LVDS3C_12P/DQ43) W10(IO_3D_36_W10/LVDS3D_6P/DQ33); U8 B7(UDQS#) C7(UDQS) D3(UDM) J1(NC0)* J9(NC1)* L1(NC2)* L9(NC3)* M7(NC4)*; U16 J1(NC0)* J9(NC1)* L1(NC2)* L9(NC3)* M7(NC4)*; U22 J1(NC0)* J9(NC1)* L1(NC2)* L9(NC3)* M7(NC4)*; U28 J1(NC0)* J9(NC1)* L1(NC2)* L9(NC3)* M7(NC4)*; U32 J1(NC0)* J9(NC1)* L1(NC2)* L9(NC3)* M7(NC4)*; U40 B7(UDQS#) C7(UDQS) D3(UDM) J1(NC0)* J9(NC1)* L1(NC2)* L9(NC3)* M7(NC4)*; U56 5(N/C)

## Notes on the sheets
sheet 17
- 12V Input
- 0.9V  30A
- VFB=0.6V
- Link/ACT
- Speed
- 1.03V 8A
- Link/ACT
- Speed
- Link/ACT
- Speed
- VFB=0.6V
- 1.8V 8A
- 1.8V
- VFB=0.6V
- 3.0V 2A
- VFB=0.6V
- 1.5V 8A
- VFB=0.6V
